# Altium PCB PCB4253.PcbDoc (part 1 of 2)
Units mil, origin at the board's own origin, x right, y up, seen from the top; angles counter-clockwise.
Board outline 1181.1 x 2007.87 mil, 6 copper layers (Top Layer, Signal Layer 2, GND Layer 3, PWR Layer 4, Signal Layer 5, Bottom Layer), stack 65.197 mil thick; 84 components, 108 nets, 396 pads, 435 vias.
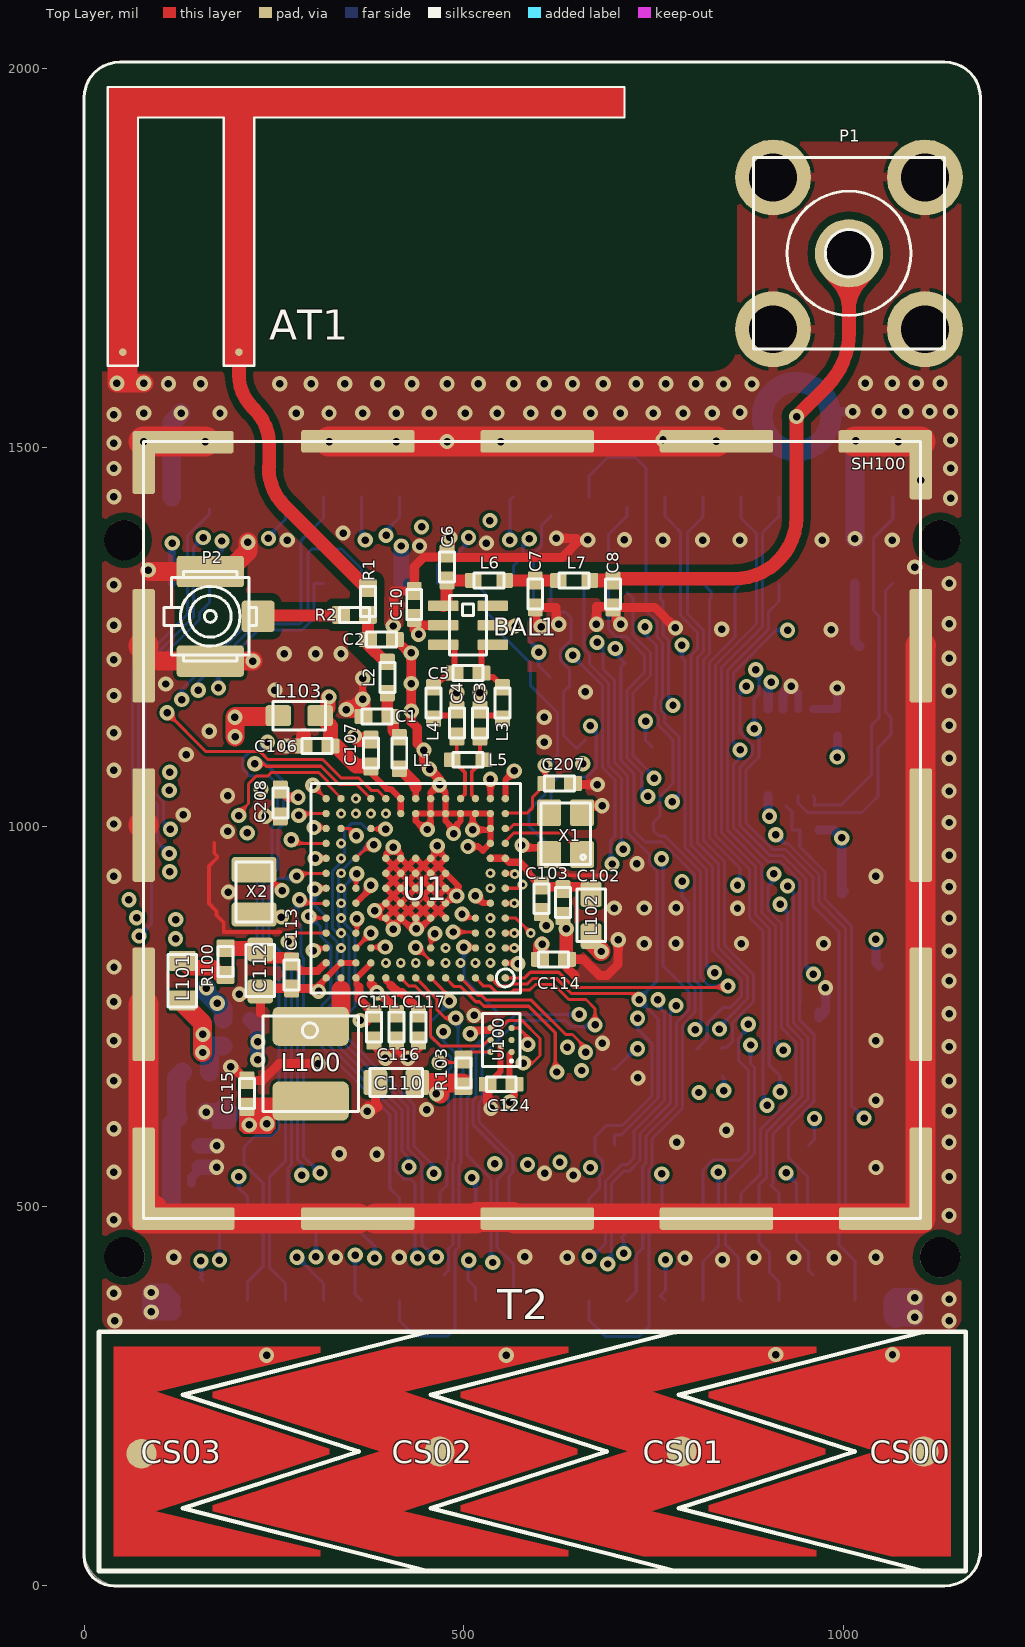
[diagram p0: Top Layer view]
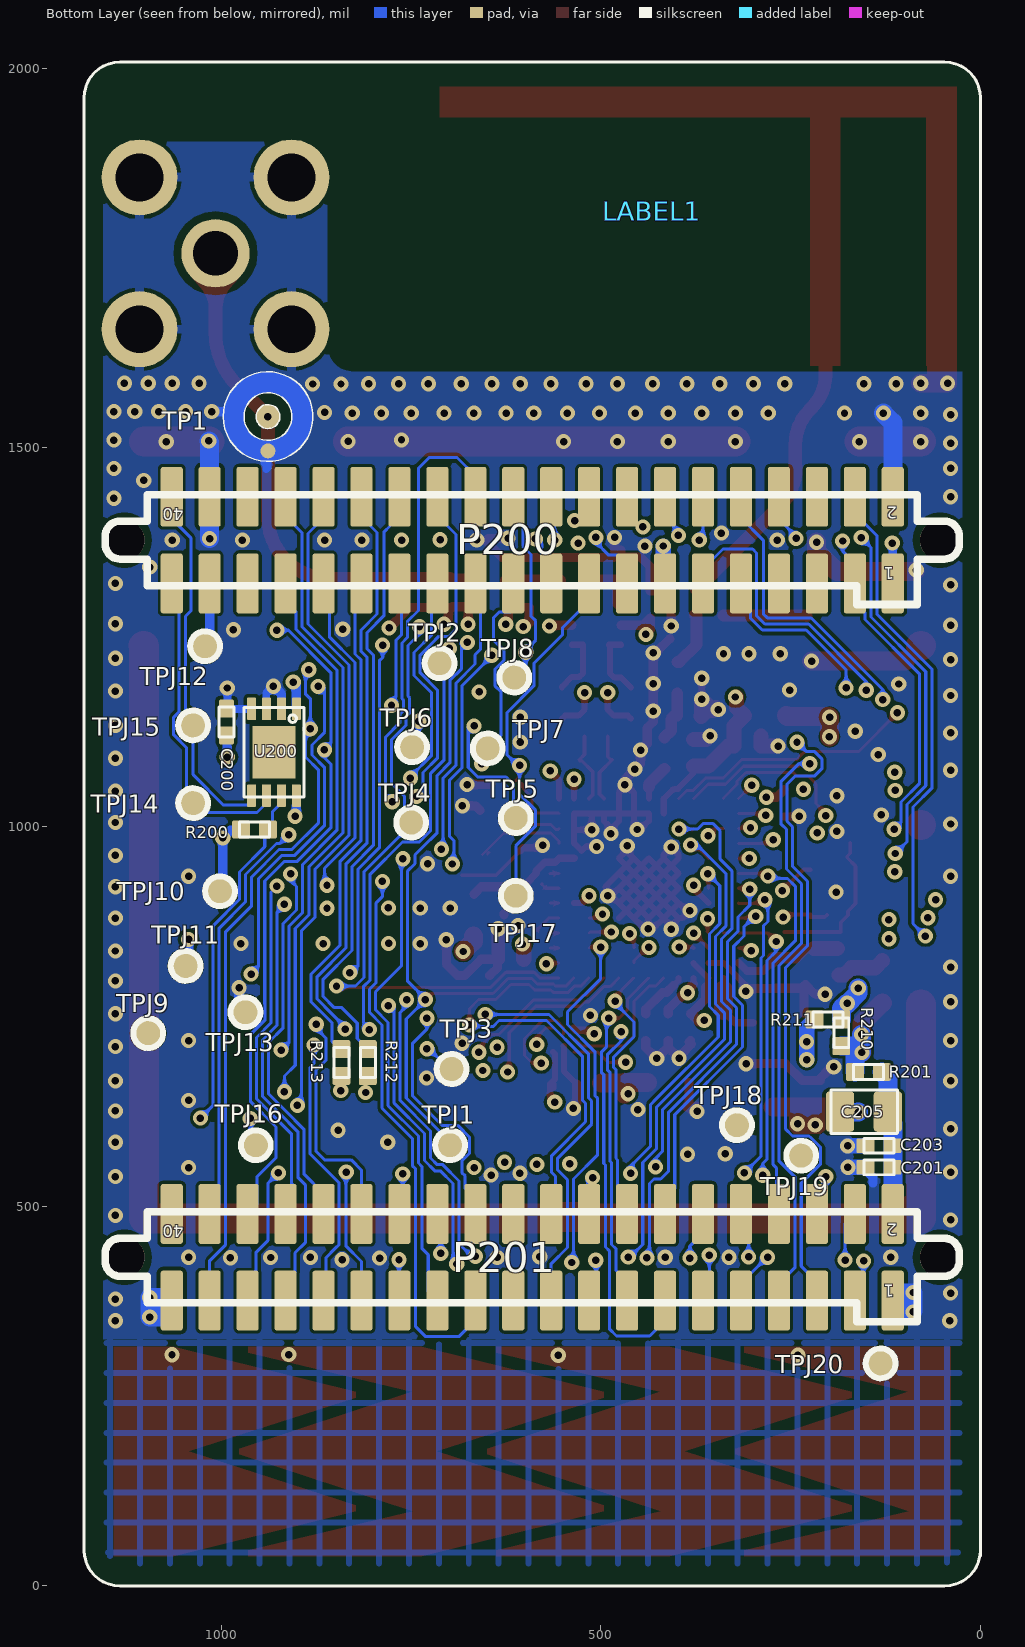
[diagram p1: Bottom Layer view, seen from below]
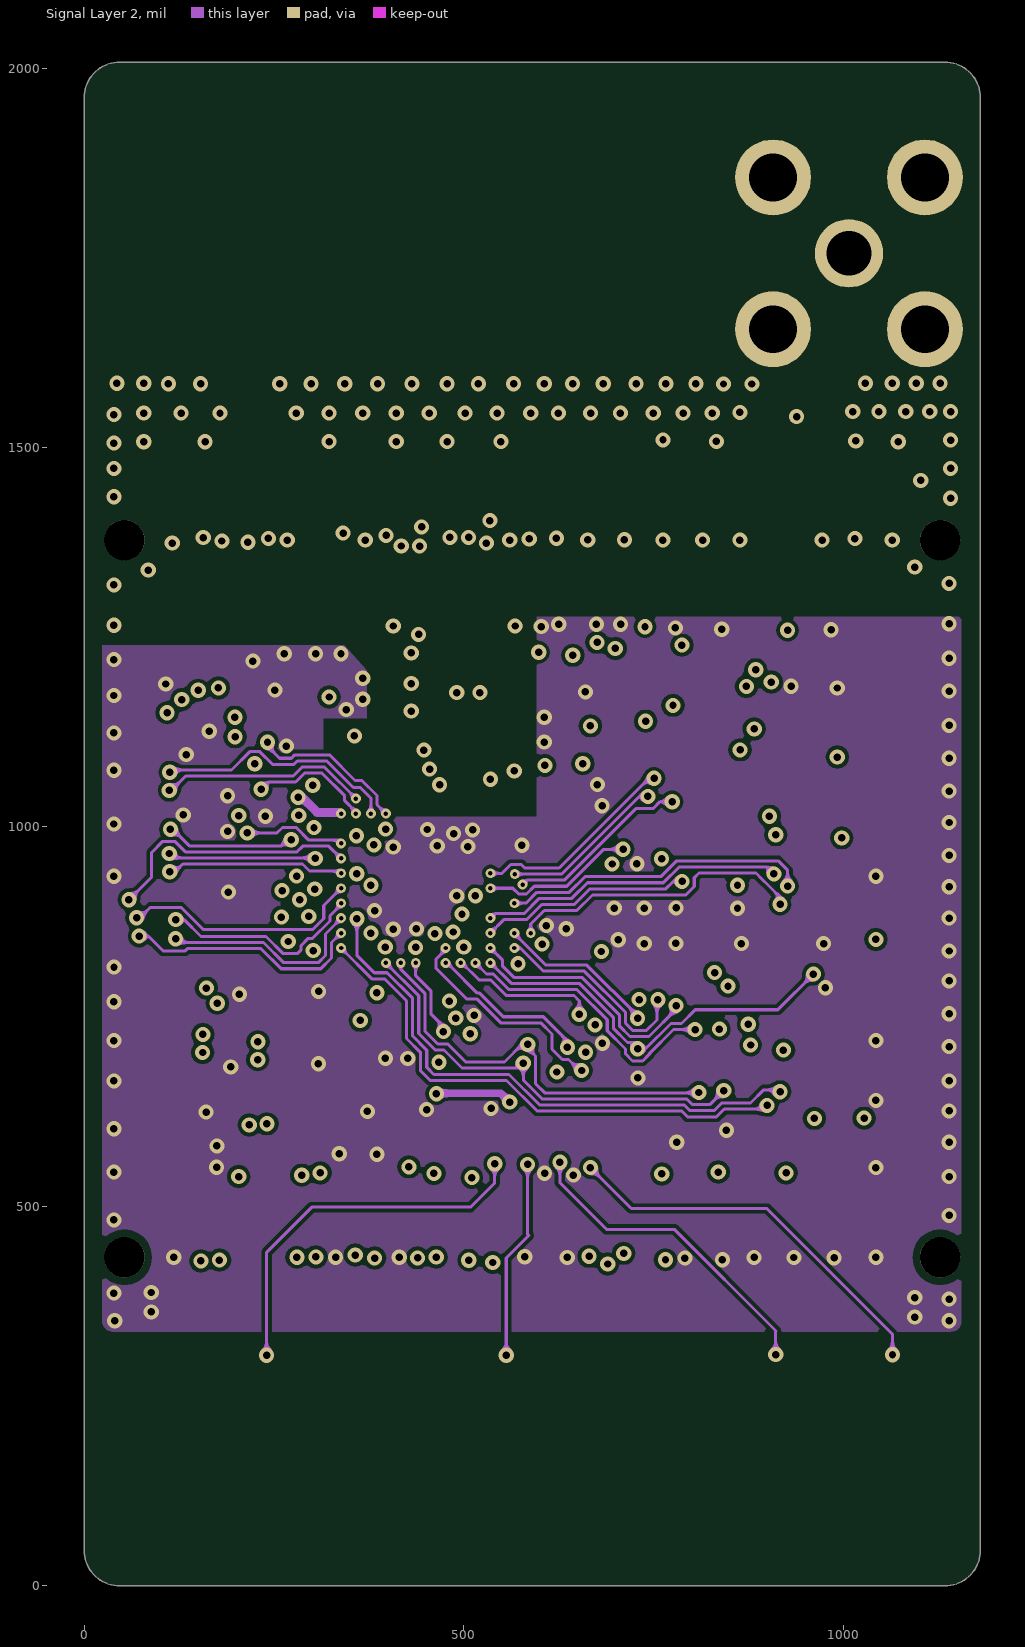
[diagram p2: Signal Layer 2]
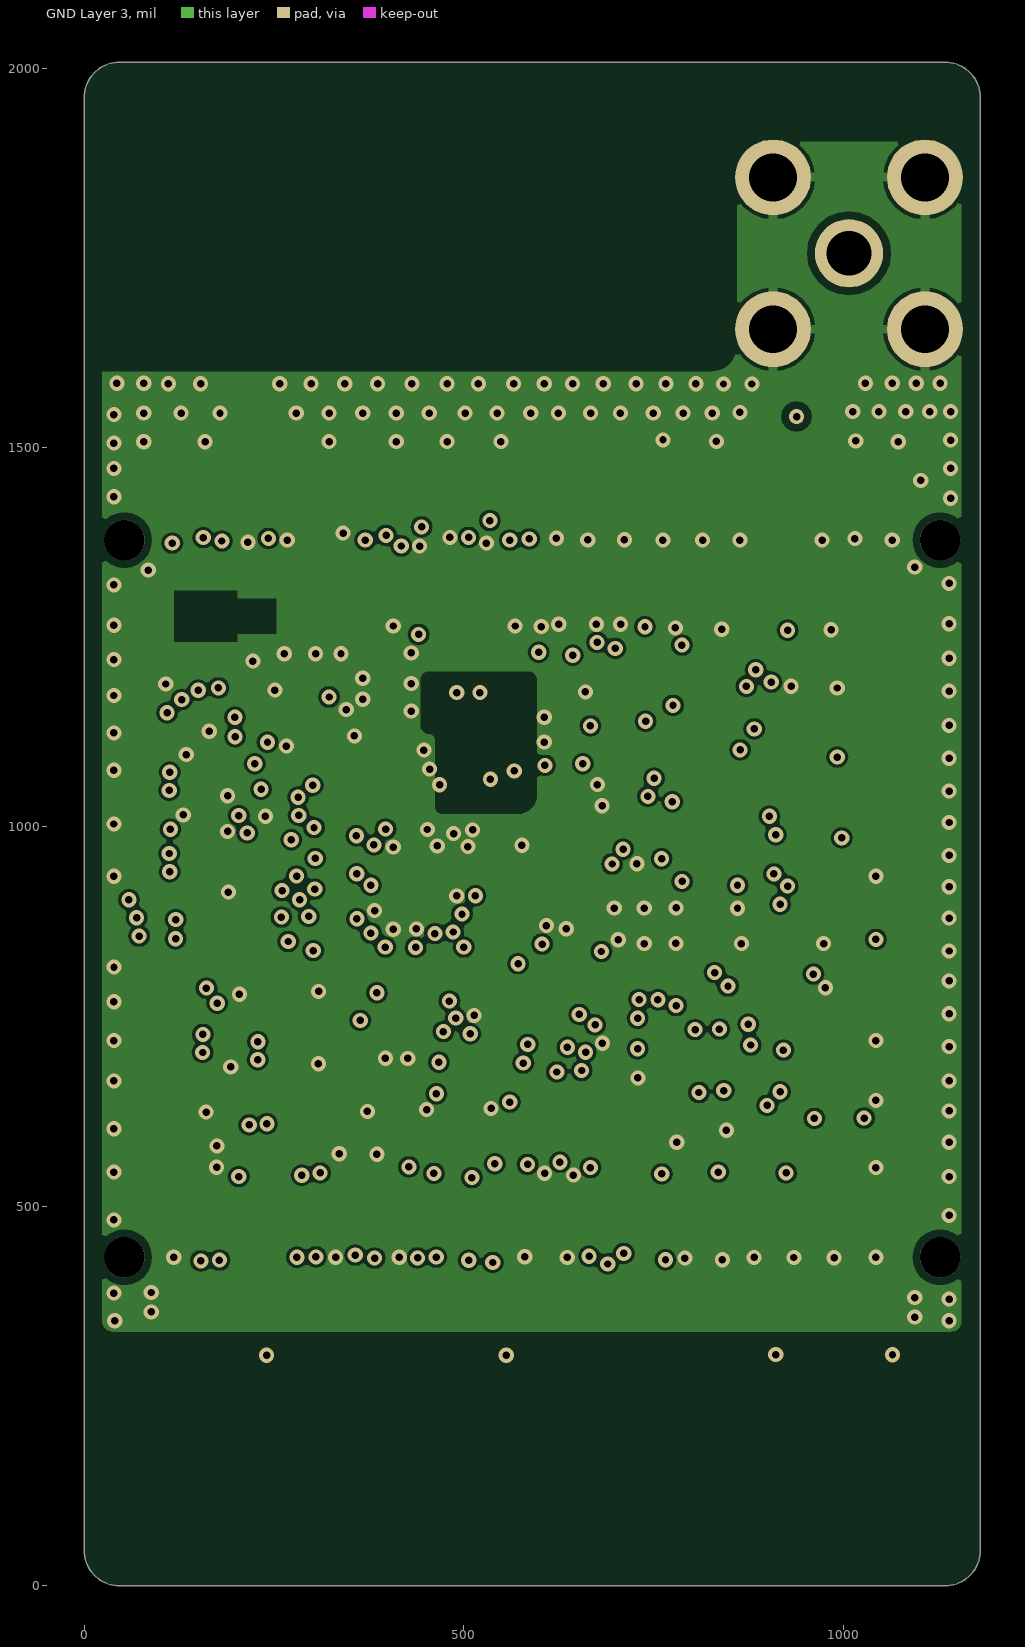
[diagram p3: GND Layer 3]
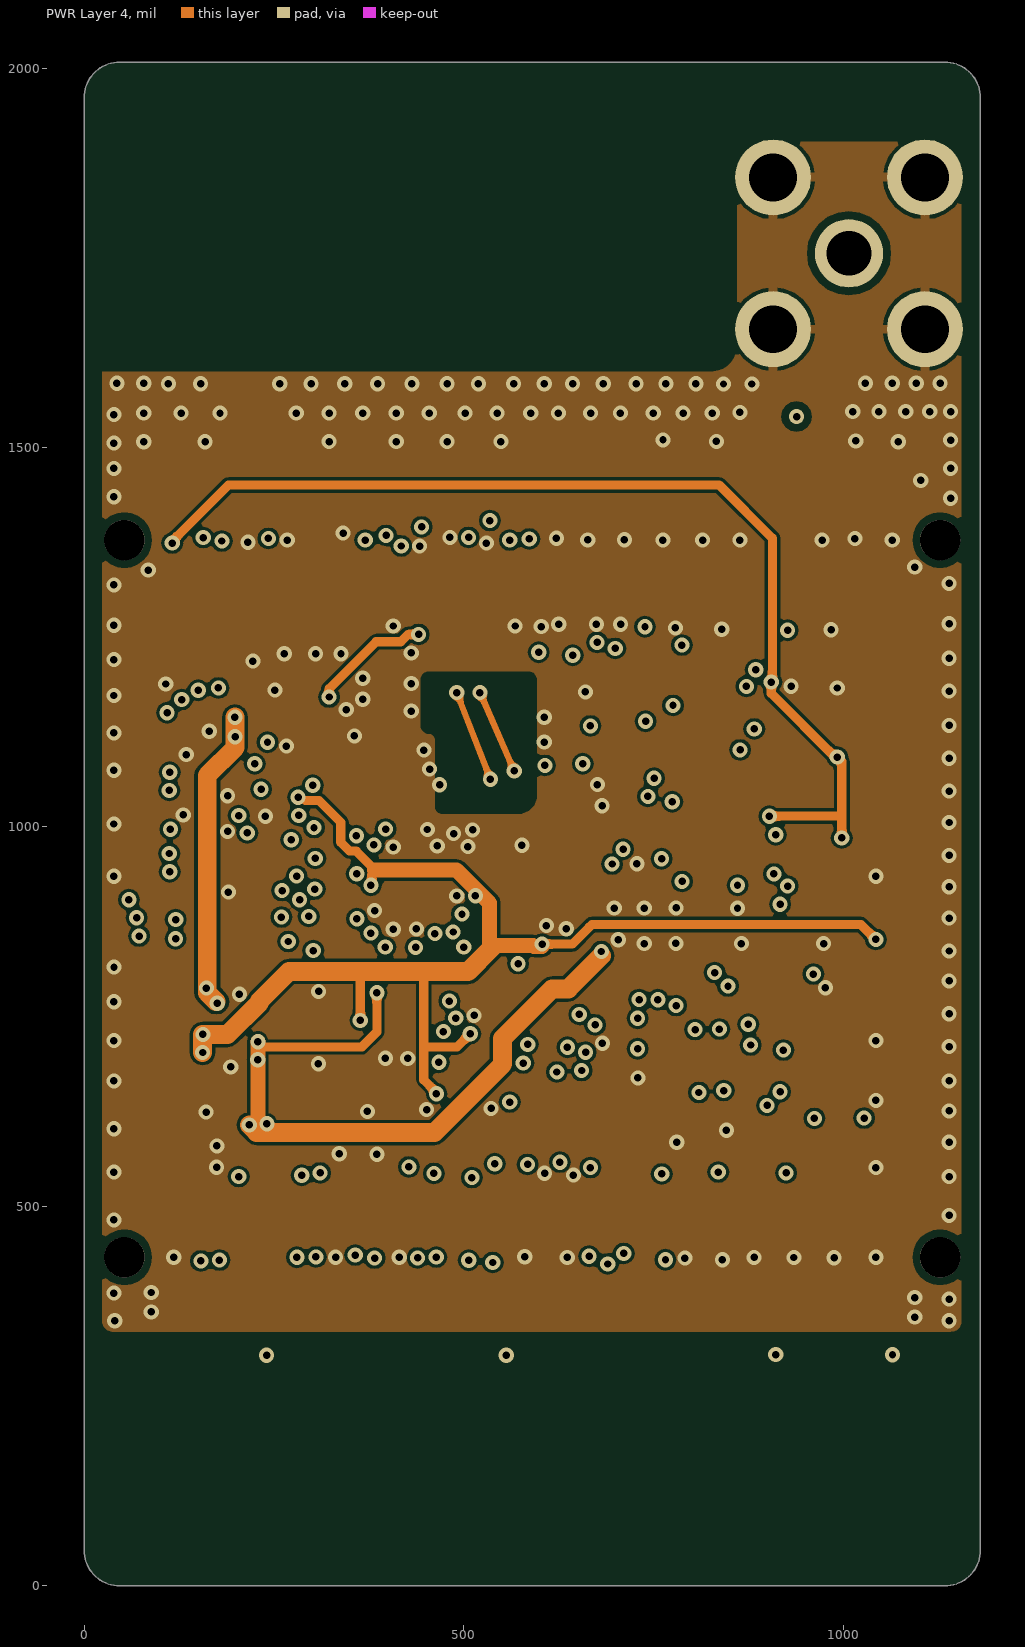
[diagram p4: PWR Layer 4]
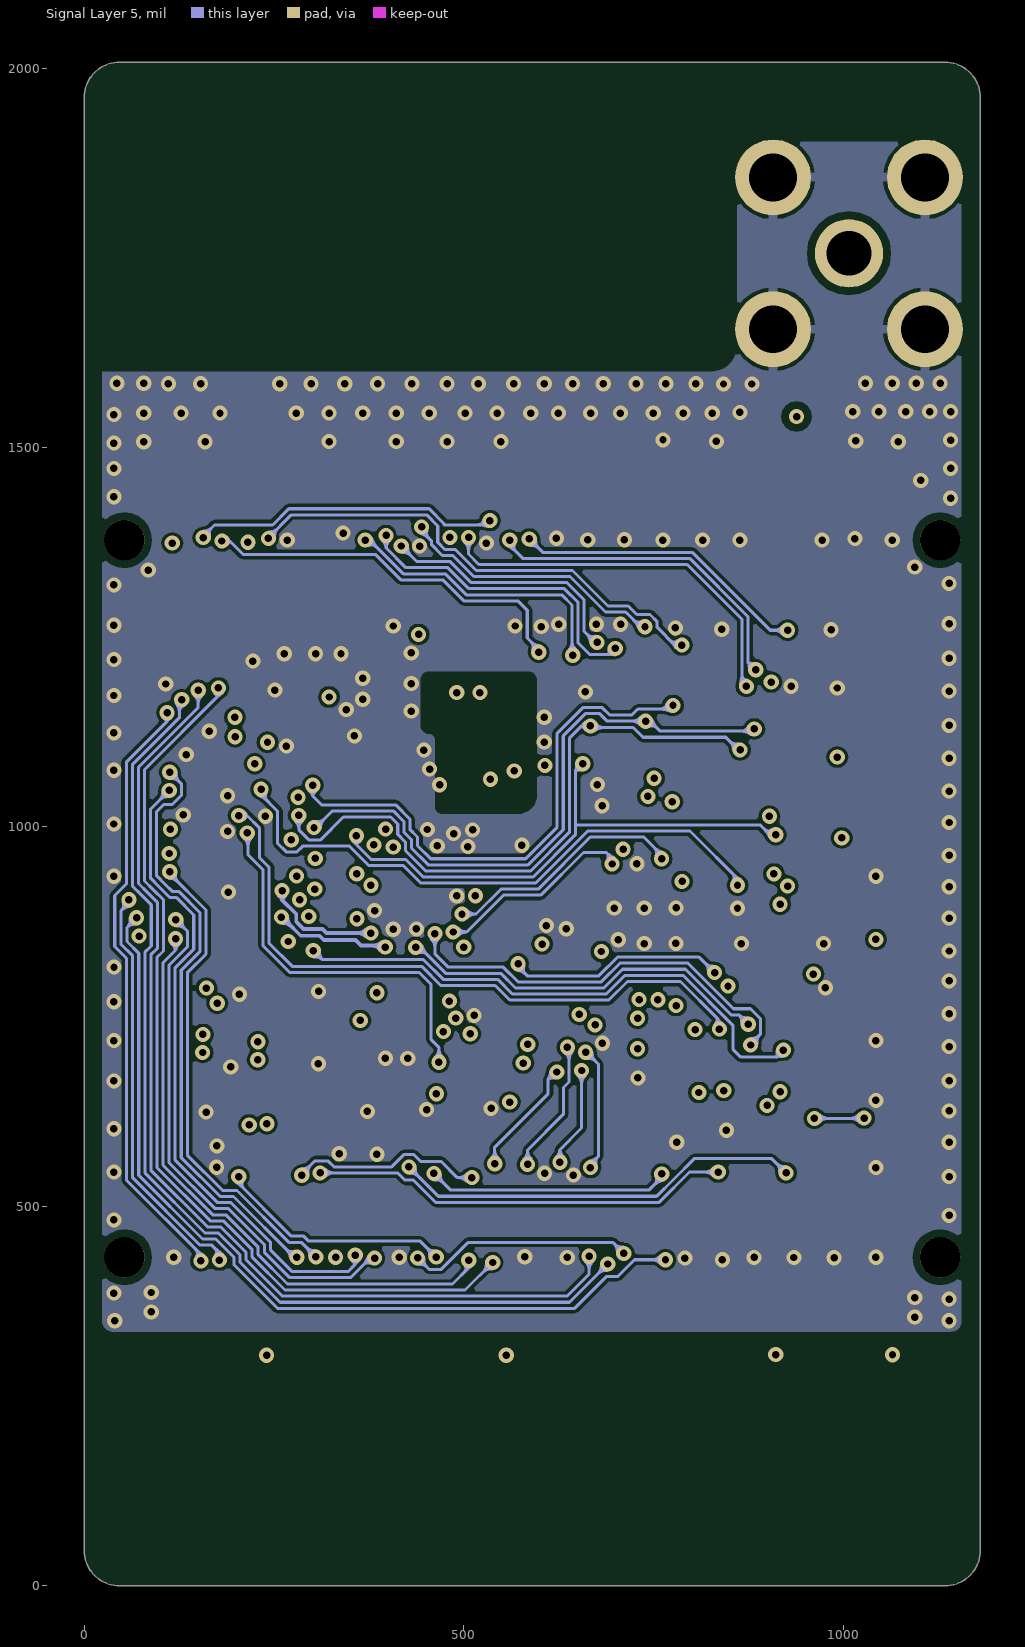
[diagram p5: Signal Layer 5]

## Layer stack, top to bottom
Top Solder: solder mask 0.3937, Solder Resist, Dk 3.5
Top Layer: signal copper 1.378
Dielectric 1: prepreg 3.5433, FR-4, Dk 4.2
Signal Layer 2: signal copper 1.378
Dielectric 2: core 7.0866, Dk 4.2
GND Layer 3: signal copper 1.378
Dielectric 3: prepreg 35.6693, FR-4, Dk 4.2
PWR Layer 4: signal copper 1.378
Dielectric 5: core 7.0866, Dk 4.2
Signal Layer 5: signal copper 1.378
Dielectric 6: prepreg 3.5433, Dk 4.2
Bottom Layer: signal copper 1.378
Bottom Solder: solder mask 0.3937, Solder Resist, Dk 3.5

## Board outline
0,47.24 ccw(c47.24,47.24) 47.24,0 1133.86,0 ccw(c1133.86,47.24) 1181.1,47.24 1181.1,1960.63 ccw(c1133.86,1960.63) 1133.86,2007.87 47.24,2007.87 ccw(c47.24,1960.63) 0,1960.63

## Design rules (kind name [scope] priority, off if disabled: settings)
Clearance Clearance_to_Holes [InPadClass('NPTH')] p1: gap=10
Clearance Clearance_NetP2_1 [InNet('NetP2_1')] p2: gap=9.84
Clearance Clearance_NetC8 [InNet('NetC8_1')] p3: gap=9.84
Clearance Clearance_Net_AT1_1 [InNet('NetAT1_1')] p4: gap=9.84
Clearance Clerance_Polygon_GND3 [InNamedPolygon('GND_3')] p5: gap=5
Clearance Clerance_Polygon_GND2 [InNamedPolygon('GND_2')] p6: gap=5
Clearance Clerance_Polygon_GND1 [InNamedPolygon('GND_L2')] p7: gap=5
Clearance Clerance_Polygon_GND4 [InNamedPolygon('GND_4')] p8: gap=5
Clearance Clearance_General [All] p9: gap=4
HoleToHoleClearance HoleToHoleClearance_ANT1toPAD [Incomponent ('ANT1') vs ISpad] p1: gap=0 allowstackedmicrovias=TRUE
HoleToHoleClearance HoleToHoleClearance_U1toVIA_1 [InComponent ('U1') vs IsVia] p2: gap=0 allowstackedmicrovias=TRUE
HoleToHoleClearance [All] p3: gap=10 allowstackedmicrovias=TRUE
MinimumSolderMaskSliver [All] p1: minsoldermaskwidth=4
PolygonConnect PolygonConnect_SH100 [InComponent('SH100')] p1: connectstyle=Direct reliefconductorwidth=10 reliefentries=4 polygonreliefangle="90 Angle" airgapwidth=5
PolygonConnect PolygonConnect_P1 [InComponent('P1')] p2: connectstyle=Relief reliefconductorwidth=12 reliefentries=4 polygonreliefangle="90 Angle" airgapwidth=5
PolygonConnect Polygon_VIA_Connect [IsVia] p3: connectstyle=Direct reliefconductorwidth=10 reliefentries=4 polygonreliefangle="90 Angle" airgapwidth=10
PolygonConnect PolygonConnect_General [All] p4: connectstyle=NoConnect reliefconductorwidth=10 reliefentries=4 polygonreliefangle="90 Angle" airgapwidth=5
RoutingVias [All] p1: holewidth=9.84 width=20 viastyle="Through Hole" minholewidth=9.84 minwidth=20 maxholewidth=39.37 maxwidth=59.06
SilkToSilkClearance [All] p1: silktosilkclearance=4
SilkToSolderMaskClearance [IsPad] p1: minsilkscreentomaskgap=4 clearancetoexposedcopper=TRUE
SolderMaskExpansion [All] p1: expansion=2
Width [All] p1: maxlimit=200 minlimit=4 preferedwidth=5
26 further rules are at their usual default settings.

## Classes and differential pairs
net class WSTK_P[45..0]: WSTK_P18 WSTK_P19 WSTK_P32 WSTK_P38 WSTK_P39 WSTK_P40
net class WSTK_F[21..0]: WSTK_F4 WSTK_F15 WSTK_F16
net class RADIO_PF[15..0]: RADIO_PF0 RADIO_PF1 RADIO_PF2 RADIO_PF3 RADIO_PF4 RADIO_PF5 RADIO_PF6 RADIO_PF7 RADIO_PF8 RADIO_PF9 RADIO_PF10 RADIO_PF11 RADIO_PF12 RADIO_PF13 RADIO_PF14 RADIO_PF15
net class RADIO_PD[15..8]: RADIO_PD8 RADIO_PD9 RADIO_PD10 RADIO_PD11 RADIO_PD12 RADIO_PD13 RADIO_PD14 RADIO_PD15
net class RADIO_PC[11..0]: RADIO_PC0 RADIO_PC1 RADIO_PC2 RADIO_PC3 RADIO_PC4 RADIO_PC5 RADIO_PC6 RADIO_PC7 RADIO_PC8 RADIO_PC9 RADIO_PC10 RADIO_PC11
net class RADIO_PB[15..6]: RADIO_PB6 RADIO_PB7 RADIO_PB8 RADIO_PB9 RADIO_PB10 RADIO_PB11 RADIO_PB12 RADIO_PB13 RADIO_PB14 RADIO_PB15
net class RADIO_PA[9..0]: RADIO_PA0 RADIO_PA1 RADIO_PA2 RADIO_PA3 RADIO_PA4 RADIO_PA5 RADIO_PA6 RADIO_PA7 RADIO_PA8 RADIO_PA9
component class "04_ WSTK Connectors & B": C200 C201 C203 C205 R200 R201 TPJ1 TPJ2 TPJ3 TPJ4 TPJ5 TPJ6 TPJ7 TPJ8 TPJ9 TPJ10 TPJ11 TPJ12 TPJ13 TPJ14 TPJ15 TPJ16 TPJ17 TPJ18 TPJ19 TPJ20 U200
component class "03_ EFR32 Signal Assign": 180 C124 C207 R103 R203 R204 R213 RP200 T2 U1
component class "02_ RF, Antenna & Power": AT1 BAL1 C1 C2 C3 C4 C5 C6 C7 C8 C10 C102 C103 C106 C107 C110 C111 C112 C113 C114 C115 C116 C117 C208 L1 L2 L3 L4 L5 L6 L7 L100 L101 L102 L103 P1 P2 R1 R2 R100 R210 R211 SH100 TP1 X1 X2
component class "01_ Title Page": PCB1
net class RADIO_PI[3..0]: RADIO_PI0 RADIO_PI1 RADIO_PI2 RADIO_PI3
net class RADIO_PJ[15..14]: RADIO_PJ14 RADIO_PJ15
net class RADIO_PK[2..0]: RADIO_PK0 RADIO_PK1 RADIO_PK2
pad class NPTH: P200-M1 P200-M2 P201-M1 P201-M2

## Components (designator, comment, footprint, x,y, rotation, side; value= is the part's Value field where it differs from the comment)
AT1 "INVERTED_F" ANT_INV_F_2.4_GHZ_17.3MM_MIR 31.1,1607.87 r0 top locked net-tie
BAL1 "0900BL15C050" BALUN_JOH_0900BL15 505.91,1265.75 r0 top
C1 "cfg" C0402_L 385.83,1145.67 r0 top
C2 "cfg" C0402_L 391.73,1247.05 r180 top
C3 "cfg" C0402_L 521.65,1136.81 r270 top
C4 "cfg" C0402_L 491.14,1136.81 r270 top
C5 "cfg" C0402_L 505.91,1202.76 r180 top
C6 "cfg" C0402_L 478.35,1342.52 r90 top
C7 "cfg" C0402_L 594.49,1307.09 r270 top
C8 "cfg" C0402_L 696.85,1307.09 r270 top
C10 "cfg" C0402_L 435.04,1293.31 r90 top
C102 "100P" C0402_L 631.1,900.34 r270 top
C103 "10P" C0402_L 602.59,905.44 r270 top
C106 "220N" C0402_L 306.81,1106.57 r180 top
C107 "10P" C0402_L 377.95,1097.44 r90 top
C110 "10U" C0603_L 411.42,663.39 r180 top
C111 "1U" C0402_L 381.89,736.22 r270 top
C112 "10U" C0603_L 232.28,811.02 r270 top
C113 "10N" C0402_L 273.62,805.12 r270 top
C114 "1U" C0402_L 618.54,825.66 r0 top
C115 "4U7" C0402_L 214.57,648.62 r90 top
C116 "100N" C0402_L 411.42,736.22 r270 top
C117 "1U" C0402_L 440.95,736.22 r270 top
C124 "100N" C0402_L 549.66,661.05 r180 top
C200 "100N" C0402_L 993.39,1138.37 r90 bottom
C201 "100N" C0402_L 133.86,551.64 r0 bottom
C203 "100N" C0402_L 133.86,579.99 r0 bottom
C205 "10U" C0805_L 153.54,625 r0 bottom
C207 "100N" C0402_L 626.68,1057.35 r0 top
C208 "100N" C0402_L 258.61,1031.55 r270 top
L1 "cfg" COIL_0402_L 415.35,1097.44 r90 top
L2 "cfg" COIL_0402_L 399.61,1196.85 r90 top
L3 "cfg" COIL_0402_L 551.18,1163.39 r270 top
L4 "cfg" COIL_0402_L 460.63,1163.39 r270 top
L5 "cfg" COIL_0402_L 505.91,1088.58 r0 top
L6 "cfg" COIL_0402_L 533.46,1324.8 r180 top
L7 "cfg" COIL_0402_L 645.67,1324.8 r180 top
L100 "4U7" COIL_MUR_LQH3NP_1212 298.59,688.08 r270 top
L101 "CBF102WB" COIL_WURTH_CBF_0603_L 129.37,797.53 r90 top
L102 "BLM18AG601SN1" COIL_MUR_BLM18_0603 668.2,883.69 r90 top
L103 "BLM18AG601SN1" COIL_MUR_BLM18_0603 283.46,1146.65 r0 top
LABEL1 "Comment" LABEL_4CORNERS_19.0X6.0 433.07,1811.02 r180 bottom
P1 "SMA" TE_SMA_1814832_TH_VER 1007.87,1755.9 r0 top locked
P2 "U.FL" COAX_HIROSE_U.FL_CL331-0471 166.34,1277.56 r270 top
P200 "SOCKET_2X20_1.27MM_SMD" SAM_SFC-120-T2-D-A-2X20_SNUM 590.55,1377.95 r0 bottom
P201 "SOCKET_2X20_1.27MM_SMD" SAM_SFC-120-T2-D-A-2X20_SNUM 590.55,433.07 r0 bottom
R1 "0R" R0402_L 374.02,1297.24 r90 top
R2 "0R" R0402_L 356.3,1279.53 r180 top
R100 "1R" R0402_L 186.5,822.54 r90 top
R103 "330K" R0402_L 499.79,676.08 r90 top
R200 "10K" R0402_L 956.5,996.6 r0 bottom
R201 "0R" R0402_L 147.64,677.17 r0 bottom
R210 "0R" R0402_L 183.39,728.96 r270 bottom
R211 "0R" R0402_L 201.11,746.28 r0 bottom
R212 "100R" R0402_L 807.24,689.59 r90 bottom
R213 "100R" R0402_L 842.11,689.77 r90 bottom
SH100 "RF_SHIELD_FRAME_BMI-S-203-F" RF_SHIELD_FRAME_BMI-S-203-F_PCB4100 590.55,996.06 r0 top locked
T2 "TOUCH SLIDER" TOUCH_SLIDER2_28.0X7.0-4 19.69,19.69 r0 top
TP1 "RF_TEST_POINT" TP_INGUN_50_OHM_CLOSED 938.78,1540.75 r180 bottom
TPJ1 "TPJ_SMD" TP_1.0_SMD 698.82,580.71 r90 bottom
TPJ2 "TPJ_SMD" TP_1.0_SMD 712.6,1215.75 r90 bottom
TPJ3 "TPJ_SMD" TP_1.0_SMD 696.85,681.1 r90 bottom
TPJ4 "TPJ_SMD" TP_1.0_SMD 750,1005.91 r90 bottom
TPJ5 "TPJ_SMD" TP_1.0_SMD 612.2,1011.81 r90 bottom
TPJ6 "TPJ_SMD" TP_1.0_SMD 748.82,1105.12 r90 bottom
TPJ7 "TPJ_SMD" TP_1.0_SMD 649.21,1103.54 r90 bottom
TPJ8 "TPJ_SMD" TP_1.0_SMD 614.17,1196.85 r90 bottom
TPJ9 "TPJ_SMD" TP_1.0_SMD 1096.46,728.35 r90 bottom
TPJ10 "TPJ_SMD" TP_1.0_SMD 1001.97,915.35 r90 bottom
TPJ11 "TPJ_SMD" TP_1.0_SMD 1047.24,816.93 r90 bottom
TPJ12 "TPJ_SMD" TP_1.0_SMD 1021.65,1238.19 r90 bottom
TPJ13 "TPJ_SMD" TP_1.0_SMD 968.5,755.91 r90 bottom
TPJ14 "TPJ_SMD" TP_1.0_SMD 1037.4,1031.5 r90 bottom
TPJ15 "TPJ_SMD" TP_1.0_SMD 1037.4,1133.86 r90 bottom
TPJ16 "TPJ_SMD" TP_1.0_SMD 954.72,580.71 r90 bottom
TPJ17 "TPJ_SMD" TP_1.0_SMD 612.2,909.45 r90 bottom
TPJ18 "TPJ_SMD" TP_1.0_SMD 320.87,607.09 r90 bottom
TPJ19 "TPJ_SMD" TP_1.0_SMD 236.22,566.93 r90 bottom
TPJ20 "TPJ_SMD" TP_1.0_SMD 131.5,293.31 r90 bottom
U1 "EFR32MG2_BGA125_0A" BGA125_M050_7.0X7.0 437.01,919.29 r180 top
U100 "MX25R8035F" BGA8_M040_1.24x1.75_WLCSP 549.51,719.31 r180 top
U200 "24AA024" TDFN8_M050_2.0X3.0_EP 930.8,1098.47 r270 bottom
X1 "38.400 MHz" X_SSS_DSX211SH_2.05X1.65-4 634.53,991.23 r90 top
X2 "32.768kHz" X_MCS_CM8V-T1A 224.08,914.32 r90 top

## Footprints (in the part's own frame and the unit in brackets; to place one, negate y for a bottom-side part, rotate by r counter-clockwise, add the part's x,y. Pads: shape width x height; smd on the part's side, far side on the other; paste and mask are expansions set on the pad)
ANT_INV_F_2.4_GHZ_17.3MM_MIR [mil] "Antenna inverted F, 2.4 GHz, 17.3 mm (MIR)"
  round 10 smd paste-5 mask-5: 1(173,17.72) 2(20.01,17.72)
  Top Layer region: 0.36,367.2 681,367.2 681,327.07 193.36,327.07 193.36,0 153.36,0 153.36,327.07 40.36,327.07 40.36,0 20.36,0 0.36,0
  silkscreen extent 0,0 681,367
BALUN_JOH_0900BL15 [mil] "BALUN JOHANSON 0900BL15 0805"
  rrect20% 40x14 smd: 1(-32.5,25.59) 2(-32.5,0) 3(-32.5,-25.59) 4(32.5,-25.59) 5(32.5,0) 6(32.5,25.59)
  silkscreen extent -25,-39 25,39, body extent -27,-41 27,41, height 32
BGA8_M040_1.24x1.75_WLCSP [mm] "BGA, 8 pin. U100"
  round 0.21 smd mask+0.051: A1(-0.35,0.4) A3(0.35,0.4) B2(0,0.2) C1(-0.35,0) C3(0.35,0) D2(0,-0.2) E1(-0.35,-0.4) E3(0.35,-0.4)
  silkscreen extent -0.63,-0.89 0.63,0.88, body extent -0.63,-0.89 0.63,0.88, height 0.52
BGA125_M050_7.0X7.0 [mm] "(BGA125N7X7P0.5)"
  round 0.25 smd: A1(-3,3) A2(-2.5,3) A3(-2,3) A4(-1.5,3) A5(-1,3) A6(-0.5,3) A7(0,3) A8(0.5,3) A9(1,3) A10(1.5,3) A11(2,3) A12(2.5,3) A13(3,3) B1(-3,2.5) B2(-2.5,2.5) B3(-2,2.5) B4(-1.5,2.5) B5(-1,2.5) B6(-0.5,2.5) B7(0,2.5) B8(0.5,2.5) B9(1,2.5) B10(1.5,2.5) B11(2,2.5) B12(2.5,2.5) B13(3,2.5) C1(-3,2) C2(-2.5,2) C3(-2,2) C5(-1,2) C6(-0.5,2) C10(1.5,2) C11(2,2) C12(2.5,2) C13(3,2) D1(-3,1.5) D2(-2.5,1.5) D3(-2,1.5) D11(2,1.5) D12(2.5,1.5) D13(3,1.5) E1(-3,1) E2(-2.5,1) E3(-2,1) E5(-1,1) E6(-0.5,1) E7(0,1) E8(0.5,1) E9(1,1) E12(2.5,1) E13(3,1) F1(-3,0.5) F2(-2.5,0.5) F5(-1,0.5) F6(-0.5,0.5) F7(0,0.5) F8(0.5,0.5) F9(1,0.5) F11(2,0.5) F12(2.5,0.5) F13(3,0.5) G1(-3,0) G2(-2.5,0) G5(-1,0) G6(-0.5,0) G7(0,0) G8(0.5,0) G9(1,0) G11(2,0) G12(2.5,0) G13(3,0) H1(-3,-0.5) H2(-2.5,-0.5) H5(-1,-0.5) H6(-0.5,-0.5) H7(0,-0.5) H8(0.5,-0.5) H9(1,-0.5) H12(2.5,-0.5) H13(3,-0.5) J1(-3,-1) J2(-2.5,-1) J5(-1,-1) J6(-0.5,-1) J7(0,-1) J8(0.5,-1) J9(1,-1) J11(2,-1) J12(2.5,-1) J13(3,-1) K1(-3,-1.5) K2(-2.5,-1.5) K12(2.5,-1.5) K13(3,-1.5) L1(-3,-2) L2(-2.5,-2) L10(1.5,-2) L12(2.5,-2) L13(3,-2) M1(-3,-2.5) M2(-2.5,-2.5) M3(-2,-2.5) M4(-1.5,-2.5) M5(-1,-2.5) M6(-0.5,-2.5) M7(0,-2.5) M8(0.5,-2.5) M9(1,-2.5) M10(1.5,-2.5) M11(2,-2.5) M12(2.5,-2.5) M13(3,-2.5) N1(-3,-3) N2(-2.5,-3) N3(-2,-3) N4(-1.5,-3) N5(-1,-3) N6(-0.5,-3) N7(0,-3) N8(0.5,-3) N9(1,-3) N10(1.5,-3) N11(2,-3) N12(2.5,-3) N13(3,-3)
  silkscreen extent -3.5,-3.5 3.5,3.5, body extent -3.5,-3.5 3.5,3.5, height 1.01
C0402_L [mm] "Chip Capacitor, 2-Leads, Body 1.0x0.5mm, IPC High Density"
  rrect20% 0.6x0.5 smd mask+0.051: 1(-0.45,0) 2(0.45,0)
  silkscreen extent -0.5,-0.25 0.5,0.25, body extent -0.5,-0.25 0.5,0.25, height 0.6
C0603_L [mm] "Capacitor, 0603, High Density (C)"
  rrect25% 0.8x0.85 smd: 1(-0.7,0) 2(0.7,0)
  silkscreen extent -0.88,-0.48 0.87,0.48, body extent -0.88,-0.48 0.87,0.48, height 0.95
C0805_L [mm] "Capacitor, 0805"
  rrect25% 0.95x1.35 smd: 1(-0.8,0) 2(0.8,0)
  silkscreen extent -1.12,-0.72 1.1,0.72, body extent -1.1,-0.72 1.1,0.72, height 1.45
COAX_HIROSE_U.FL_CL331-0471 [mm] "COAX_HIROSE_U.FL_CL331-0471"
  rrect20% 1.05x1.1 smd mask+0.051: 1(0,1.6)
  rrect20% 1.05x2.25 smd mask+0.051: 2(-1.5,0) 3(1.5,0)
  Top Layer pour cut-out: -0.85,0.9 0.85,0.9 0.85,0.9 0.85,-1.2 -0.85,-1.2 -0.85,-1.2
  silkscreen extent -1.5,-1.55 1.5,1.55, body extent -1.3,-1.55 1.3,1.3, height 0.9
COIL_0402_L [mm] "COIL_0402_L"
  rrect20% 0.55x0.5 smd mask+0.051: 1(-0.525,0) 2(0.525,0)
  silkscreen extent -0.5,-0.25 0.5,0.25, body extent -0.5,-0.25 0.5,0.25, height 0.6
COIL_MUR_BLM18_0603 [mm] "COIL_MUR_BLM18P_0603"
  rrect25% 0.85x0.7 smd mask+0.051: 1(-0.7,0) 2(0.7,0)
  silkscreen extent -0.88,-0.48 0.87,0.48, body extent -0.88,-0.48 0.87,0.48, height 0.95
COIL_MUR_LQH3NP_1212 [mm] "COIL_MUR_LQH3NP_1212"
  rrect30% 1.3x2.55 smd mask+0.051: 1(-1.25,0) 2(1.25,0)
  silkscreen extent -1.6,-1.6 1.6,1.6, body extent -1.6,-1.6 1.6,1.6, height 1.5
COIL_WURTH_CBF_0603_L [mm] "COIL_WURTH_CBF_0603_L (= L0603_0.8_L)"
  rrect10% 0.67x0.88 smd: 1(-0.665,0) 2(0.665,0)
  silkscreen extent -0.87,-0.48 0.87,0.48, body extent -0.87,-0.48 0.87,0.48, height 0.95
LABEL_4CORNERS_19.0X6.0 [mil]
R0402_L [mm] "Chip Resistor, 2-Leads, Body 1.0x0.5mm, IPC High Density"
  rrect20% 0.6x0.6 smd mask+0.051: 1(-0.45,0) 2(0.45,0)
  silkscreen extent -0.5,-0.25 0.5,0.25, body extent -0.5,-0.25 0.5,0.25, height 0.6
RF_SHIELD_FRAME_BMI-S-203-F_PCB4100 [mm] "RF_SHIELD_FRAME_BMI-S-203-F"
  rrect20% 0.75x3.8 smd paste+0 mask+0.05: 1(-13.005,-5.835) 1(-13.005,0.165) 1(-13.005,6.165) 1(13.005,-5.835) 1(13.005,0.165) 1(13.005,6.165)
  rrect20% 0.75x3.4 smd paste+0 mask+0.05: 1(-13.005,-11.659) 1(13.005,-11.659)
  rrect20% 0.75x2.1 smd paste+0 mask+0.05: 1(-13.005,12.294)
  oval 0.75x0.254 smd paste+0 mask+0.05: 1(-13.004,12.994) 1(12.994,12.994) 1(12.994,12.994) 1(12.994,12.994)
  rrect20% 3.375x0.75 smd paste+0 mask+0.05: 1(-11.684,12.979)
  rrect20% 3.4x0.75 smd paste+0 mask+0.05: 1(-11.659,-13.005)
  rrect20% 3.8x0.75 smd paste+0 mask+0.05: 1(-5.835,-13.005) 1(-5.835,13.005) 1(0.165,-13.005) 1(0.165,13.005) 1(6.165,-13.005) 1(6.165,13.005)
  rrect20% 3.1x0.75 smd paste+0 mask+0.05: 1(11.811,-13.005)
  rrect20% 3.125x0.75 smd paste+0 mask+0.05: 1(11.811,13.005)
  rrect20% 0.75x2.3 smd paste+0 mask+0.05: 1(13.005,12.217)
  silkscreen extent -13.01,-13.01 13,13, body extent -13,-13 12.99,12.99, height 5.08
SAM_SFC-120-T2-D-A-2X20_SNUM [mm]
  rrect20% 0.74x2 smd mask+0.05: 1(-12.065,1.45) 2(-12.065,-1.45) 3(-10.795,1.45) 4(-10.795,-1.45) 5(-9.525,1.45) 6(-9.525,-1.45) 7(-8.255,1.45) 8(-8.255,-1.45) 9(-6.985,1.45) 10(-6.985,-1.45) 11(-5.715,1.45) 12(-5.715,-1.45) 13(-4.445,1.45) 14(-4.445,-1.45) 15(-3.175,1.45) 16(-3.175,-1.45) 17(-1.905,1.45) 18(-1.905,-1.45) 19(-0.635,1.45) 20(-0.635,-1.45) 21(0.635,1.45) 22(0.635,-1.45) 23(1.905,1.45) 24(1.905,-1.45) 25(3.175,1.45) 26(3.175,-1.45) 27(4.445,1.45) 28(4.445,-1.45) 29(5.715,1.45) 30(5.715,-1.45) 31(6.985,1.45) 32(6.985,-1.45) 33(8.255,1.45) 34(8.255,-1.45) 35(9.525,1.45) 36(9.525,-1.45) 37(10.795,1.45) 38(10.795,-1.45) 39(12.065,1.45) 40(12.065,-1.45)
  round 1.35 hole 1.35 unplated paste-5.563 mask-5.563: M1(13.652,0) M2(-13.652,0)
  silkscreen extent -14.29,-1.53 14.29,2.15, body extent -14.65,-1.58 14.65,2.25, height 4.57
TDFN8_M050_2.0X3.0_EP [mm] "TDFN8_M050_2.0x3.0_EP"
  rrect20% 0.75x0.3 smd mask+0.051: 1(-1.45,0.75) 2(-1.45,0.25) 3(-1.45,-0.25) 4(-1.45,-0.75) 5(1.45,-0.75) 6(1.45,-0.25) 7(1.45,0.25) 8(1.45,0.75)
  rect 1.75x1.45 smd mask+0.051: 9(0,0)
  silkscreen extent -1.5,-1 1.5,1, body extent -1.5,-1 1.5,1, height 1.01
TE_SMA_1814832_TH_VER [mm]
  round 2.286 hole 1.5: 1(0,0)
  round 2.54 hole 1.6: 2(-2.54,-2.54) 3(2.54,-2.54) 4(2.54,2.54) 5(-2.54,2.54)
  silkscreen extent -3.2,-3.2 3.2,3.2, body extent -3.2,-3.2 3.2,3.2, height 9.5
TOUCH_SLIDER2_28.0X7.0-4 [mm]
  round 1 smd paste-0.51 mask-0.51: 1(1.424,3.924) 2(11.4,4) 3(19.5,4) 4(27.6,4)
  Top Layer region: 28.5,7.5 26.5,7.5 20.4,6 20.4,5.8 26,4 20.4,2.2 20.4,2 26.5,0.5 28.5,0.5 28.5,2
  Top Layer region: 24,7.5 18.2,7.5 12.1,6 12.1,5.8 17.7,4 12.1,2.2 12.1,2 18.2,0.5 24,0.5 24,0.7 18.5,2 24.3,3.9 24.3,4.1 18.538,6 24,7.3
  Top Layer region: 15.7,7.5 9.9,7.5 3.8,6 3.8,5.8 9.4,4 3.8,2.2 3.8,2 9.9,0.5 15.7,0.5 15.7,0.7 10.2,2 16,3.9 16,4.1 10.238,6 15.7,7.3
  Top Layer region: 7.4,7.5 1.6,7.5 0.5,7.5 0.5,4 0.5,0.5 1.6,0.5 7.4,0.5 7.4,0.7 1.9,2 7.7,3.9 7.7,4.1 1.938,6 7.4,7.3
  silkscreen extent 0,0 29,8
TP_1.0_SMD [mm] "Test Point, 1.0 mm, SMD"
  round 1 smd paste-0.501: 1(0,0)
  silkscreen extent -0.5,-0.5 0.5,0.5
TP_INGUN_50_OHM_CLOSED [mm] "TP_INGUN_50_OHM_CLOSED"
  round 0.8 / inner round 0.508 / far side round 0.508 hole 0.25 mask+0: 1(0,0)
  round 0.5 smd paste-0.255 mask-0.41: 2(0,-1.15)
  Top Layer lines w0.7: 0,-1.15 cw(c0,0) -1.15,0 cw(c0,0) 0,-1.15
  silkscreen extent -1.5,-1.5 1.5,1.5
X_MCS_CM8V-T1A [mm] "Crystal MCS CM8V-T1A (2 pin)"
  rrect25% 0.8x1.5 smd paste-0.15 mask+0.051: 1(-0.75,0)
  rrect25% 0.85x1.5 smd paste-0.15 mask+0.051: 2(0.75,0)
  silkscreen extent -1,-0.6 1,0.6, body extent -1,-0.6 1,0.6, height 0.97
X_SSS_DSX211SH_2.05X1.65-4 [mm] "X_SSS_DSX211SH_2.05X1.65-4"
  rrect20% 0.9x0.8 smd mask+0.051: 1(-0.7,-0.55) 2(0.7,-0.55) 3(0.7,0.55) 4(-0.7,0.55)
  silkscreen extent -1.02,-0.82 1.02,0.82, body extent -1.07,-0.87 1.07,0.87, height 0.51

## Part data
AT1: library part ANT_INVERTED_F
C1 C2 C3 C4 C5 C6 C7 C8 C10 C102 C103 C106 C107 C111 C113 C114 C115 C116 C117 C124 C200 C201 C203 C207 C208: library part C0402
C110 C112: library part C0603
C205: library part C0805
L1 L2 L3 L4 L5 L6 L7: library part L0402
L100: library part LQH3NP
L102 L103: library part BLM18AG
P1: library part SMA_TH
P2: library part HIROSE_U.FL
R1 R2 R100 R103 R200 R201 R210 R211 R212 R213: library part R0402
T2: library part TOUCH_SLIDER
TP1: library part TP_RF
U100: library part MX25R8035
X1: library part DSX211SH
X2: library part CM8V-T1A

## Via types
v1: diameter 20, hole 9.84, Top Layer to Bottom Layer, tented both sides, 403 vias
v2: diameter 13/13 (per signal layer), hole 5.91, Top Layer to Signal Layer 2, tented both sides, 31 vias
v3: diameter 13/13 (per signal layer), hole 5.91, Top Layer to Signal Layer 2, tented top, 1 vias

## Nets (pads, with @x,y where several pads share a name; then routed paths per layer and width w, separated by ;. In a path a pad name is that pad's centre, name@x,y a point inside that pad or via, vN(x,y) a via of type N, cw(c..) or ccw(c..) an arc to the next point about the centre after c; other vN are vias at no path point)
3V3: C200.1 P200.1 R200.2 TPJ10.1 U200.1 U200.8 | length 1662.7
  PWR Layer 4 w12: v1(116.14,1374.02) 116.14,1376.53 190.4,1450.79 836.61,1450.79 907,1380.4 907,1189.45 v1(905.51,1190.94) 905.51,1176.12 989.49,1092.14 v1(992.5,1092.14) 998.37,1086.27 998.37,1013.84 ; v1(903,1014.22) 996.22,1014.22 997.49,1012.96 998.37,1013.84 ; v1(998.37,985.68) 998.37,1013.84
  Bottom Layer w10: P200.1@115.55,1320.87 115.55,1373.43 v1(116.14,1374.02)
  Bottom Layer w12: U200.8@901.27,1041.39 901.27,1012.96 902.54,1014.22 v1(903,1014.22) ; R200.2@968.5,996.06 987.98,996.06 v1(998.37,985.68) 998.37,911.75 TPJ10.1@1001.97,915.35 ; v1(992.5,1092.14) C200.1@992.5,1119.71
  Bottom Layer w12.01: U200.1@901.27,1155.56 901.51,1155.8 901.51,1186.95 v1(905.51,1190.94) ; U200.1@901.28,1156.1 901.33,1156.14 U200.1@901.33,1168.69
5V: P200.37 TPJ12.1 | length 85.2
  Bottom Layer w13: P200.37@1015.55,1320.87 1015.55,1244.29 TPJ12.1@1021.65,1238.19
BOARD_ID_SCL: P200.39 TPJ14.1 U200.6 | length 423.9
  Bottom Layer w4: U200.6@940.64,1041.39 940.64,1031.63 953.16,1019.11 1025.01,1019.11 TPJ14.1@1037.4,1031.5 1045.86,1039.96 1045.86,1104.18 1063.09,1121.4 1063.09,1144.5 1055.86,1151.72 1055.86,1311.18 P200.39@1065.55,1320.87
BOARD_ID_SDA: P200.40 TPJ15.1 U200.5 | length 489.3
  Bottom Layer w4: U200.5@960.33,1041.39 962.27,1039.44 U200.5@962.27,1028.74 ; U200.5@962.27,1028.29 U200.5@962.27,1028.74 ; P200.40@1065.55,1435.04 1065.55,1406.1 1040.35,1380.91 1040.35,1284.5 1047.34,1277.51 1047.34,1143.8 TPJ15.1@1037.4,1133.86 1037.4,1068.87 997.27,1028.74 U200.5@962.27,1028.74
BOARD_ID_WP: R200.1 TPJ16.1 U200.7 | length 563.8
  Signal Layer 5 w4: v1(962.22,616.12) 1022.17,616.12 1022.47,616.42 v1(1027.8,616.42)
  Bottom Layer w4: U200.7@925.07,1027.62 933.07,1019.62 933.07,996.06 942.98,996.06 942.98,974.12 976.28,940.82 976.28,904.72 1011,870 1011,633.22 v1(1027.8,616.42) ; TPJ16.1@954.72,580.71 962.22,588.21 v1(962.22,616.12)
GND: AT1.2 BAL1.5 C1.1 C2.1 C6.2 C7.2 C8.2 C10.2 C102.2 C103.2 C106.2 C107.2 C110.2 C111.2 C112.2 C113.2 C114.2 C115.2 C116.2 C117.2 C124.2 C200.2 C201.2 C203.2 C205.2 C207.2 C208.2 P1.2 P1.3 P1.4 P1.5 P2.2 P2.3 P200.2 P200.38 P201.1 P201.39 SH100.1 TP1.2 TPJ13.1 U1.A13 U1.B11 U1.B12 U1.E5 U1.E6 U1.E7 U1.E8 U1.E9 U1.F5 U1.F6 U1.F7 U1.F8 U1.F9 U1.G5 U1.G6 U1.G7 U1.G8 U1.G9 U1.H5 U1.H6 U1.H7 U1.H8 U1.H9 U1.J5 U1.J6 U1.J7 U1.J8 U1.J9 U1.K2 U1.L2 U1.M2 U1.M3 U1.M4 U1.M5 U1.M6 U1.M7 U1.N5 U1.N6 U100.B2 U200.2 U200.3 U200.4 X1.2 X1.4 | length 7957.8
  Top Layer w5: 171.5,979.06 171.5,965.39 175.5,961.39 175.5,959.39 164.5,948.39 164.5,899.06 174.5,889.06 174.5,883.64 184.1,874.04 184.1,861.61 258.26,861.61 ; v1@236.84,1014.22 v1(239,1014.22) ; C1.1@368.11,1145.67 C1.1@370.08,1145.67 ; X1.4@606.3,968.5 638.32,936.48 683.19,936.48
  Top Layer w7.99: C124.2@531.94,661.05 548.78,677.89 548.78,710.71 U100.B2@549.51,711.44
  Top Layer w8: v1(309.07,783.29) 309.07,791.36 U1.A13@318.9,801.18 U1.B12@338.58,820.87 U1.B11@358.27,820.87 ; v1(367.13,1168.31) v1(367.13,1195.87) ; v1(407.48,865.16) v1@407.48,870.08 ; v1(465.46,975.11) 469.19,975.11 470.63,973.67 466,969.04 v1@466.54,968.5 ; U1.E5@476.38,879.92 466.54,889.76 ; v1(505.86,974.26) 519.84,974.26 525.59,968.5 U1.K2@535.43,978.35 U1.L2@535.43,998.03 ; U1.E9@397.64,879.92 392.72,879.92 v1(382.87,889.76) 387.8,889.76 U1.F9@397.64,899.61 ; U1.E9@397.64,879.92 407.48,889.76 ; U1.E9@397.64,879.92 v1@407.48,870.08 ; U1.F9@397.64,899.61 407.48,889.76 ; U1.F9@397.64,899.61 407.48,909.45 ; v1@407.48,870.08 U1.E8@417.32,879.92 ; 407.48,889.76 U1.E8@417.32,879.92 ; 407.48,889.76 U1.F8@417.32,899.61 ; 407.48,909.45 U1.G9@397.64,919.29 407.48,929.13 ; 407.48,909.45 U1.F8@417.32,899.61 ; 407.48,909.45 U1.G8@417.32,919.29 ; 407.48,929.13 U1.H9@397.64,938.98 407.48,948.82 ; 407.48,929.13 U1.G8@417.32,919.29 ; 407.48,929.13 U1.H8@417.32,938.98 ; 407.48,948.82 U1.J8@417.32,958.66 ; 407.48,948.82 U1.J9@397.64,958.66 397.64,963.58 v1(407.48,973.43) 417.32,963.58 U1.J8@417.32,958.66 ; 407.48,948.82 U1.H8@417.32,938.98 ; U1.E8@417.32,879.92 427.17,889.76 ; U1.E8@417.32,879.92 432.09,865.16 433.83,866.91 435.01,865.73 v1(437.84,865.73) ; U1.F8@417.32,899.61 427.17,889.76 ; U1.F8@417.32,899.61 427.17,909.45 ; U1.G8@417.32,919.29 427.17,909.45 ; U1.G8@417.32,919.29 427.17,929.13 ; U1.H8@417.32,938.98 427.17,929.13 ; U1.H8@417.32,938.98 427.17,948.82 ; U1.J8@417.32,958.66 427.17,948.82 ; 427.17,889.76 U1.E7@437.01,879.92 ; 427.17,889.76 U1.F7@437.01,899.61 ; 427.17,909.45 U1.F7@437.01,899.61 ; 427.17,909.45 U1.G7@437.01,919.29 ; 427.17,929.13 U1.G7@437.01,919.29 ; 427.17,929.13 U1.H7@437.01,938.98 ; 427.17,948.82 U1.H7@437.01,938.98 ; 427.17,948.82 U1.J7@437.01,958.66 446.85,948.82 ; U1.E7@437.01,879.92 437.84,879.09 v1(437.84,865.73) ; U1.E7@437.01,879.92 446.85,889.76 ; U1.F7@437.01,899.61 446.85,889.76 ; U1.F7@437.01,899.61 446.85,909.45 ; U1.G7@437.01,919.29 446.85,909.45 ; U1.G7@437.01,919.29 446.85,929.13 ; U1.H7@437.01,938.98 446.85,929.13 ; U1.H7@437.01,938.98 446.85,948.82 ; v1(437.84,865.73) 439,865.73 440.18,866.91 441.93,865.16 U1.E6@456.69,879.92 ; 446.85,889.76 U1.E6@456.69,879.92 ; 446.85,889.76 U1.F6@456.69,899.61 ; 446.85,909.45 U1.F6@456.69,899.61 ; 446.85,909.45 U1.G6@456.69,919.29 ; 446.85,929.13 U1.G6@456.69,919.29 ; 446.85,929.13 U1.H6@456.69,938.98 ; 446.85,948.82 U1.H6@456.69,938.98 ; 446.85,948.82 U1.J6@456.69,958.66 ; U1.E6@456.69,879.92 466.54,889.76 ; U1.F6@456.69,899.61 466.54,889.76 ; U1.F6@456.69,899.61 466.54,909.45 ; U1.G6@456.69,919.29 466.54,909.45 ; U1.G6@456.69,919.29 466.54,929.13 ; U1.H6@456.69,938.98 466.54,929.13 ; U1.H6@456.69,938.98 466.54,948.82 ; U1.J6@456.69,958.66 v1@466.54,968.5 ; U1.J6@456.69,958.66 466.54,948.82 ; U1.M6@456.69,1017.72 456.69,997.91 453.04,994.26 452.33,994.97 v1(452.33,996.68) 452.33,995.97 450.62,994.26 437.01,1007.87 U1.M7@437.01,1017.72 U1.M6@456.69,1017.72 ; U1.M6@456.69,1017.72 U1.N6@456.69,1037.4 456.69,1045.28 467.06,1055.65 v1(468.4,1055.65) 468.4,1053.25 476.38,1045.28 U1.N5@476.38,1037.4 U1.M5@476.38,1017.72 ; U1.M6@456.69,1017.72 U1.M5@476.38,1017.72 ; 466.54,889.76 U1.F5@476.38,899.61 ; 466.54,909.45 U1.F5@476.38,899.61 ; 466.54,909.45 U1.G5@476.38,919.29 ; 466.54,929.13 U1.G5@476.38,919.29 ; 466.54,929.13 U1.H5@476.38,938.98 ; 466.54,948.82 U1.H5@476.38,938.98 ; 466.54,948.82 U1.J5@476.38,958.66 v1@466.54,968.5 ; U1.F5@476.38,899.61 491.14,914.37 492.7,912.8 491,911.1 v1(491,909.22) ; U1.G5@476.38,919.29 483.49,912.18 485.52,914.22 490.52,909.22 v1(491,909.22) ; U1.H5@476.38,938.98 494.12,921.23 491,918.1 492.7,916.4 491,914.7 v1(491,909.22) ; U1.M5@476.38,1017.72 476.38,1007.87 487.37,996.88 487,996.5 v1(487,991.22) 487,998.81 496.06,1007.87 U1.M4@496.06,1017.72 ; U1.M5@476.38,1017.72 U1.M4@496.06,1017.72 ; U1.M4@496.06,1017.72 U1.M3@515.75,1017.72 ; U1.M3@515.75,1017.72 512.02,1013.99 v1(512.02,996.22) 533.62,996.22 U1.L2@535.43,998.03 ; U1.M3@515.75,1017.72 U1.M2@535.43,1017.72 U1.L2@535.43,998.03
  Top Layer w10: v1@238.13,1013.84 C208.2@258.61,1013.84 ; SH100.1@360.83,484.06 SH100.1@384.1,484.06 ; SH100.1@562.7,472.13 559,475.83 SH100.1@567.22,484.06 ; v1(577,975.96) 580.71,972.25 580.71,972.44 602.36,972.44 X1.4@606.3,968.5 ; SH100.1@589.09,476.1 SH100.1@597.05,484.06
  Top Layer w12: v1(39.29,1074.8) v1@39.29,1076.77 ; v1(193.34,683.89) 196.42,683.89 C115.2@213.97,666.34 ; v1(204.76,779.73) 218.09,779.73 C112.2@230.78,792.43 ; C115.2@211.02,666.34 211.34,666.02 234.91,666.02 257.02,688.13 v1(308.81,688.13) ; 232.28,754.77 C112.2@232.28,783.46 ; C112.2@232.28,790.9 232.28,787.5 C113.2@269.69,787.5 ; C113.2@271.21,787.4 C113.2@273.62,787.4 305.12,787.4 309.07,783.45 v1(309.07,783.29) ; v1(373.38,625.16) 373.38,628.24 371.75,629.88 374.09,632.22 380.2,626.11 385.26,631.16 386.1,630.33 387,631.24 384.74,633.5 385.46,634.22 385.83,633.86 383.86,631.89 C110.2@383.86,663.39 ; C111.2@381.89,718.5 383.86,716.54 381,713.68 v1@397,697.68 ; v1(397,695.22) 411.42,709.64 C116.2@411.42,710.14 ; v1(407.5,1264.81) 407.5,1290.35 ; 407.48,1290.37 407.48,1311.02 C10.2@435.04,1311.02 435.04,1342.77 448.21,1355.95 473.4,1355.95 C6.2@473.4,1365.18 ; C2.1@409.45,1248.03 v1@431.1,1226.38 ; C116.2@411.42,718.5 C116.2@411.42,710.14 ; v1(431.1,1188.97) v1@431.1,1187.01 ; v1@431.1,1189.54 v1@431.1,1187.01 ; v1(431.12,1229.38) 428.1,1229.38 v1@431.1,1226.37 ; C117.2@440.95,718.5 C117.2@440.95,709.33 ; C117.2@441.01,709.39 C117.2@440.95,709.33 ; v1(468.4,1055.65) 468.4,1063.1 455.23,1076.26 v1(455.23,1076.36) 455.13,1076.36 447.83,1083.66 v1(447.83,1101.38) 438.98,1110.24 438.98,1130.71 431.1,1138.59 v1(431.1,1152.69) v1@431.1,1187.01 ; v1(482.07,1381.59) 482.07,1363.96 C6.2@478.35,1360.24 483.38,1355.21 630.41,1355.21 652.08,1376.87 648.6,1380.35 v1(622.43,1380.35) ; BAL1.5@538.41,1265.75 570.94,1265.75 570.01,1264.81 v1(567.94,1264.81) ; v1@599.54,1263.58 594.49,1268.62 C7.2@594.49,1289.37 622.05,1289.37 622.05,1270.85 v1@624.94,1267.96 ; C102.2@627.95,883.86 C102.2@627.95,885.83 ; C207.2@644.4,1057.35 645.84,1055.91 v1(676.48,1055.91) ; X1.2@659.17,1021.77 665.29,1027.89 v1(682.53,1027.89) ; v1@675.6,1264.45 678.38,1267.22 v1(675,1267.22) 675,1290.19 695.46,1290.19 C8.2@697.54,1288.11 ; v1@705.77,1268.45 v1(707,1267.22) v1@709.46,1267.22 ; v1@706.79,1263.23 v1@708,1264.44 ; v1@707.56,1268.35 706.15,1268.35 700.78,1273.72 700.78,1285.44 C8.2@696.85,1289.37 751.76,1289.37 v1@779.7,1261.43 ; SH100.1@1102.36,1454.72 v1(1102.36,1456.69) ; C116.2@411.42,710.14 v1(426.51,695.04) 426.66,695.04 C117.2@440.95,709.33 ; v1@431.1,1187.01 v1@431.1,1226.37
  Top Layer w12.01: v1@531.94,636.9 C124.2@531.94,661.05 ; 646.52,804.47 636.26,814.73 C114.2@636.26,825.66 657.91,825.66 679.1,804.47 689.15,804.47 703.77,819.09 v1(703.77,851.42)
  Top Layer w17.99: C114.2@635.23,825.66 v1(635.23,866.03)
  Top Layer w20: v1(266.65,1106.57) C106.2@289.09,1106.57 289.09,1119.5 ; v1(345.49,1154.59) 348.43,1157.48 v1@352.36,1153.54 ; v1(356.3,1120.08) 361.22,1115.16 C107.2@377.95,1115.16 ; C1.1@368.11,1145.67 C1.1@367.13,1146.65 ; v1@352.36,1153.54 v1(367.13,1168.31) 367.13,1147.64 368.11,1146.65 C1.1@367.13,1146.65 ; v1@352.36,1153.54 360.24,1153.54 C1.1@367.13,1146.65
  Top Layer w25: v1(78.74,1584.65) 58.07,1584.65 ; v1@86.54,1336.61 P2.2@166.34,1336.61 189.16,1336.61 216,1363.45 v1(216,1375.22) ; 98.82,1218.5 P2.3@166.34,1218.5 v1(222.44,1218.5) ; 58.07,1584.65 v1(43.31,1584.65) 43.31,1617.79 AT1.2@51.11,1625.59 58.07,1618.63 58.07,1584.65
  Top Layer w39.37: SH100.1@78.52,766.31 78.52,484.12 SH100.1@78.56,484.07 ; SH100.1@78.98,1508.07 v1(78.56,1507.66) v1(159.45,1507.66) ; SH100.1@90.55,496.06 SH100.1@78.56,484.07 ; v1(322.83,1507.87) 323.03,1508.07 SH100.1@360.83,1508.07 SH100.1@411.22,1508.07 ; SH100.1@360.83,484.06 SH100.1@78.56,484.07 ; SH100.1@384.1,484.06 516.12,484.06 518.03,485.97 565.31,485.97 567.22,484.06 SH100.1@597.05,484.06 SH100.1@827.56,484.06 ; v1(411.42,1507.87) SH100.1@411.22,1508.07 ; v1(549.21,1507.87) SH100.1@549.41,1508.07 ; SH100.1@760.8,1507.87 597.24,1507.87 SH100.1@597.05,1508.07 SH100.1@549.41,1508.07 ; SH100.1@764.86,1507.87 833.07,1507.87 v1(833.27,1508.07) SH100.1@833.68,1507.66 ; SH100.1@833.27,484.06 SH100.1@1102.13,484.06 ; SH100.1@1015.75,1507.87 1015.96,1507.66 v1(1072.83,1507.66) SH100.1@1102.15,1507.66 ; SH100.1@1102.15,484.07 1102.15,1238.37 SH100.1@1102.56,1238.78 ; SH100.1@411.22,1508.07 SH100.1@549.41,1508.07
  Signal Layer 2 w12: v1(567.94,1264.81) 570.01,1264.81 570.94,1265.75 v1@571.93,1264.76
  Bottom Layer w10: C205.2@172.76,606.81 193.43,606.81 C205.2@194.41,607.8 ; v1(931.5,1185.5) 941.12,1175.87 U200.3@941.12,1155.51 ; TP1.2@938.78,1495.47 TP1.2@939.12,1495.13 ; 943.57,1479.98 943.57,1490.69 TP1.2@940.94,1493.31 ; U200.4@960.33,1155.51 992.13,1155.51 992.13,1182.94 v1(992.31,1183.13) ; TP1.2@939.12,1495.13 939.12,1473.28 940.94,1471.46 TP1.2@940.94,1493.31 ; TP1.2@939.12,1495.13 TP1.2@940.94,1493.31
  Bottom Layer w12: U200.2@920.96,1155.56 920.96,1174.95 v1(931.5,1185.5) ; TPJ13.1@968.5,755.91 968.5,748.65 976.9,757.04 v1(976.9,788.11) ; 984.06,1540.75 990.55,1547.24 v1(1012.8,1547.24)
  Bottom Layer w12.01: 141.48,531.31 141.48,538.12 C201.2@151.57,548.21
  Bottom Layer w20: C201.2@151.57,551.64 v1(174.72,551.64) ; C203.2@151.57,579.99 174.75,579.99 v1(174.99,579.75)
  Bottom Layer w25: P201.1@114.17,364.17 116.14,362.2 88.58,362.2 88.58,385.83 105.71,385.83 P201.1@115.55,375.98 ; P200.2@115.55,1435.04 115.55,1532.87 v1(127.95,1545.28) ; v1(160.74,624.41) 161.19,624.41 161.44,624.16 191.28,624.16 C205.2@191.28,618.42 ; C205.2@185.04,625 C205.2@185.04,630.45 ; v1(1015.75,1379.92) 1015.75,1434.84 P200.38@1015.55,1435.04 1015.55,1507.46 v1(1016.73,1508.64) ; P201.39@1065.55,375.98 1065.55,355.71 1068.9,352.36 1070.87,354.33 v1(1094.49,354.33) v1(1094.49,379.92) ; P201.39@1065.55,375.98 1090.55,375.98 v1(1094.49,379.92) ; P201.39@1065.55,375.98 1069.49,379.92 v1(1094.49,379.92)
  other v1: 40.35,349.41 1139.76,349.41 88.58,361.07 1139.69,377.95 39.29,385.83 88.58,386.67 841.18,429.82 791.78,431.98 935.29,432.76 988.17,432.37 118.11,433.07 331.4,433.01 415.4,433.04 580.63,433.74 636.64,432.84 882.82,432.89 1043.31,433.07 39.29,482.28 1139.69,488.19 1139.69,539.37 644.86,541.4 606.77,543.86 39.29,545.28 1043.31,551.18 336.27,569.42 385.89,568.82 780.94,584.61 1139.69,584.65 846.46,600.39 39.29,602.36 1139.69,625.98 451.3,627.67 536.39,629.23 1043.31,639.76 39.29,665.35 1139.69,665.35 729.69,669.41 1139.69,710.63 682.97,715.04 39.29,718.5 1043.31,718.5 513.86,751.74 1139.69,753.94 39.29,769.69 1139.69,797.24 39.46,815.4 1139.69,836.61 738.19,846.46 779.88,846.57 866.14,846.46 974.41,846.46 609.28,870.12 1139.69,879.92 698.65,893.15 738.1,893.15 780.13,893.4 860.99,892.94 190.15,914.22 1139.69,921.26 39.37,935.04 1043.31,935.04 728.39,951.6 1139.69,962.6 189.21,994.24 39.37,1003.94 1139.69,1005.91 130.81,1015.86 189.21,1041.2 1139.69,1047.24 1139.69,1090.55 134.61,1095.35 606.3,1111.88 39.29,1124.02 164.86,1126.15 1139.69,1133.86 606.44,1144.48 39.29,1173.23 660.55,1177.99 1139.69,1179.13 251.51,1180.43 107.75,1188.4 39.29,1220.47 1139.69,1222.44 263.78,1228.34 305.12,1228.35 338.58,1228.35 840.28,1260.49 984.25,1259.84 779.24,1262.22 602.4,1264.09 39.29,1265.75 625.37,1267.19 1139.69,1267.72 39.29,1318.9 1139.69,1320.87 84.61,1338.54 1094.49,1342.52 442.04,1370.03 530.12,1374.14 267.72,1377.95 663.75,1378.3 711.9,1378.42 762.8,1377.95 814.96,1377.95 864.17,1377.95 972.44,1377.95 1064.96,1377.95 341.28,1387.26 1141.73,1433.07 39.37,1435.04 39.37,1472.44 1141.73,1472.44 39.37,1505.91 478.35,1507.87 762.83,1509.9 1141.73,1509.84 39.37,1543.31 78.74,1545.27 179.13,1545.28 279.53,1545.27 322.83,1545.27 367.13,1545.27 411.42,1545.27 454.72,1545.27 501.97,1545.27 544.29,1545.28 588.58,1545.27 625,1545.27 667.32,1545.27 706.69,1545.27 750,1545.27 789.37,1545.27 827.76,1545.28 864.17,1546.26 1047.24,1547.24 1082.68,1547.24 1114.17,1547.24 1141.73,1547.24 842.52,1583.66 879.92,1583.66 111.22,1583.99 153.54,1583.99 257.87,1583.99 299.21,1583.99 343.5,1583.99 386.81,1583.99 432.09,1583.99 478.35,1583.99 519.69,1583.99 565.94,1583.99 606.3,1583.99 643.7,1583.99 684.06,1583.99 727.36,1583.99 766.73,1583.99 806.1,1583.99 1029.53,1584.65 1064.96,1584.65 1096.46,1584.65 1127.95,1584.65
NetAT1_1: AT1.1 R1.2 | length 374.5
  Top Layer w18: AT1.1@204.1,1625.59 204.1,1596.07 ccw(c265.83,1596.07) 222.18,1552.42 224.61,1550 cw(c177.56,1502.95) 244.09,1502.95 244.09,1474.29 ; 243.17,1474.29 ccw(c316.06,1474.29) 264.52,1422.74 291.34,1395.92 R1.2@374.02,1313.25
NetBAL1_1: BAL1.1 C6.1 L6.2 | length 67
  Top Layer w8: C6.1@477.36,1320.87 C6.1@478.35,1321.85
  Top Layer w15.6: BAL1.1@473.41,1291.34 477.36,1295.3 C6.1@477.36,1320.87 ; C6.1@478.35,1324.8 L6.2@512.8,1324.8
NetBAL1_3: BAL1.3 C5.2 L4.1 | length 88.9
  Top Layer w8: L4.1@460.63,1184.06 473.43,1196.85 482.28,1196.85 C5.2@488.19,1202.76 488.19,1239.17 489.17,1240.16 BAL1.3@473.41,1240.16
NetBAL1_4: BAL1.4 C5.1 L3.1 | length 88.1
  Top Layer w8: BAL1.4@538.41,1240.16 523.62,1240.16 C5.1@523.62,1202.76 528.54,1197.83 538.39,1197.83 551.18,1185.04 L3.1@551.18,1184.06
NetC1_2: C1.2 L1.2 L2.1 | length 66.8
  Top Layer w15.6: C1.2@399.61,1146.65 L2.1@399.61,1176.18 ; C1.2@403.54,1145.67 407.48,1141.73 407.48,1126.97 L1.2@416.34,1118.11 ; C1.2@403.54,1146.65 C1.2@406.64,1143.55
NetC2_2: C2.2 L2.2 R1.1 R2.1 | length 74.3
  Top Layer w15.6: R1.1@374.02,1279.53 374.02,1248.03 374.02,1240.16 396.65,1217.52 L2.2@399.61,1217.52
NetC3_1: C3.1 L3.2 U1.N1 | length 211.2
  Top Layer w8: v1(521.65,1177.17) C3.1@521.65,1154.53 529.53,1146.65 547.24,1146.65 L3.2@551.18,1142.72 ; U1.N1@555.12,1037.4 555.12,1062.01 v1(566.93,1073.82)
  PWR Layer 4 w8: v1(521.65,1177.17) v1(566.93,1073.82)
NetC3_2: C3.2 L5.2 U1.N3 | length 94.4
  Top Layer w5: U1.N3@515.75,1037.4 510.97,1042.18 510.97,1072.98 L5.2@526.57,1088.58 ; C3.2@521.65,1119.09 521.65,1095.47 528.54,1088.58 L5.2@527.56,1087.6
NetC4_1: C4.1 L4.2 U1.N2 | length 206.1
  Top Layer w8: L4.2@460.63,1142.72 464.57,1146.65 483.27,1146.65 C4.1@491.14,1154.53 v1(491.14,1177.17) ; U1.N2@535.43,1037.4 v1(535.43,1062.99)
  PWR Layer 4 w8: v1(491.14,1177.17) v1(535.43,1062.99)
NetC4_2: C4.2 L5.1 U1.N4 | length 92.7
  Top Layer w5: L5.1@485.24,1088.58 501.97,1071.85 501.97,1043.31 U1.N4@496.06,1037.4 ; L5.1@487.2,1088.58 491.14,1092.52 C4.2@491.14,1119.09
NetC7_1: C7.1 L6.1 L7.2 | length 70.9
  Top Layer w15.6: L6.1@554.13,1324.8 C7.1@594.49,1324.8 L7.2@625,1324.8
NetC8_1: C8.1 L7.1 P1.1 TP1.1 | length 691.5
  Top Layer w18: L7.1@666.34,1324.8 C8.1@696.85,1324.8 699.12,1327.07 856,1327.07 ccw(c857.18,1408.67) 938.78,1407.48 TP1.1@938.78,1540.75 978.58,1580.55 ccw(c907.87,1651.26) 1007.87,1651.26 P1.1@1007.87,1755.9
NetC102_1: C102.1 C103.1 L102.2 U1.J1 U1.J2 | length 155.9
  Top Layer w10: U1.J2@535.43,958.66 U1.J1@555.12,958.66 560.34,953.44 565.38,953.44 570.87,953.44 573.86,953.44 585.11,942.2 585.11,938.78 598.43,925.46 C103.1@598.43,921.26
  Top Layer w12: C103.1@598.43,921.26 657.48,921.26 L102.2@667.32,911.42
NetC112_1: C112.1 C113.1 R100.2 U1.B13 | length 136.8
  Top Layer w10: C113.1@275.59,820.87 286.15,810.31 308.06,810.31 318.62,820.87 U1.B13@318.9,820.87
  Top Layer w15: C112.1@232.28,838.58 243.25,827.62 273.62,827.62 C113.1@273.62,822.83 C113.1@275.59,820.87
  Top Layer w20: R100.2@188.18,839.83 C112.1@219.52,839.83
NetC117_1: C117.1 U1.A9 | length 68.9
  Top Layer w8: U1.A9@397.64,797.24 U1.A9@397.64,797.97 ; U1.A9@397.64,801.18 U1.A9@397.64,797.97 ; 404.64,790.96 U1.A9@397.64,797.97
  Top Layer w12: 404.64,790.96 413.62,781.98 418.8,781.98 440.95,759.84 C117.1@440.95,753.94
NetL1_1: L1.1 U1.N7 | length 47.5
  Top Layer w8: U1.N7@437.01,1037.4 437.01,1052.17
  Top Layer w15.6: L1.1@416.34,1076.77 434.22,1058.89 cw(c427.5,1052.17) 437.01,1052.17
NetL100_1: L100.1 U1.A12 | length 89.2
  Top Layer w8: 338.58,785.43 U1.A12@338.58,801.18
  Top Layer w10: L100.1@299.21,742.13 322.83,742.13 L100.1@338.58,757.87
  Top Layer w25: L100.1@338.58,757.87 338.58,785.43
NetL101_2: L101.2 R100.1 | length 65
  Top Layer w20: L101.2@129.37,823.71 138.64,814.44 170.27,814.44 179.89,804.82 R100.1@186.5,804.82
NetP2_1: P2.1 R2.2 | length 109.7
  Top Layer w15.6: P2.1@229.33,1277.56 P2.1@230.32,1278.54
  Top Layer w15.75: P2.1@230.32,1278.54 R2.2@338.58,1278.54
NetU1_K1: U1.K1 X1.1 | length 122.7
  Top Layer w4: U1.K1@555.12,978.35 555.12,980.97 566.11,991.96 627.89,991.96 X1.1@656.19,963.67 ; X1.1@647.64,966.54 X1.1@649.61,964.57
NetU1_L1: U1.L1 X1.3 | length 78.6
  Top Layer w4: U1.L1@555.12,998.03 556.71,996.44 559.28,996.44 565.88,1003.05 607.61,1003.05 612.88,1008.32 X1.3@612.88,1018.79 ; X1.3@606.3,1018.79 X1.3@606.3,1023.62
PAVDD: L103.1 R210.1 R211.1 | length 536.2
  Top Layer w25: v1(198.97,1118.8) 198.82,1118.95 v1(198.82,1144.69) 199.79,1145.66 254.91,1145.66 L103.1@255.91,1146.65
  PWR Layer 4 w25: v1@174.18,769.77 162.35,781.6 162.35,1068.06 198.97,1104.68 v1(198.97,1118.8) 198.82,1118.95 v1(198.82,1144.69) v1@199,1144.5
  Bottom Layer w25: v1(161.14,787.69) 161.14,781.37 177.2,765.31 177.41,765.51 175.62,767.29 v1(175.62,767.75) 176.44,767.75 183.39,760.8 R210.1@183.39,746.68
RADIO_PA0: P200.19 P201.36 TPJ5.1 U1.M13 | length 2389.4
  Top Layer w4: v1@280.93,1017.72 U1.M13@318.9,1017.72
  Signal Layer 5 w4: v1(283,1015.22) 283,996.54 296.88,982.66 311.16,982.66 341.71,1013.22 403.96,1013.22 413.33,1003.84 413.33,990.59 413.19,990.45 413.19,990.34 423.48,980.05 423.48,968.8 450.14,942.15 588.44,942.15 639.37,993.08 639.37,1116.81 655.82,1133.26 v1(667.13,1133.26) 669.42,1130.97 723.6,1130.97 736.35,1118.22 845.57,1118.22 v1@863.19,1100.6 ; v1(586.65,1379.51) 604.21,1361.95 801.22,1361.95 903.96,1259.22 v1(927,1259.22)
  Bottom Layer w4: P200.19@565.55,1328.71 565.55,1343.79 578.36,1356.6 578.36,1375.6 582.27,1379.51 v1(586.65,1379.51) ; TPJ5.1@612.2,1011.81 615.22,1014.82 615.22,1056.25 624.9,1065.93 662.34,1065.93 674.9,1078.48 674.9,1125.5 v1(667.13,1133.26) ; 856,1082.9 856,998.98 900.73,954.25 917.6,954.25 943,928.85 943,766.73 942.82,766.54 942.82,745.27 962,726.09 962,638.52 928.25,604.77 928.25,564.14 953.22,539.17 953.22,502.48 P201.36@965.55,490.16 ; 856.2,1082.9 864.41,1091.11 v1(864.41,1101.64) ; v1@866.61,1100.14 856,1110.74 856,1203.41 911.81,1259.22 v1(927,1259.22)
RADIO_PA1: P200.20 P201.37 TPJ6.1 U1.L13 | length 2268.1
  Top Layer w4: v1(303,999.22) 315.74,999.22 317.91,997.05 U1.L13@318.9,998.03
  Signal Layer 5 w4: v1(303,999.22) 305.32,999.22 327.32,1021.22 407.27,1021.22 421.33,1007.16 421.33,993.52 431.48,983.37 431.48,972.12 453.45,950.15 585.13,950.15 631.37,996.39 631.37,1120.13 660.51,1149.26 679.55,1149.26 689.38,1139.42 v1(739.94,1139.42) 739.94,1143.35 741,1144.41 759.19,1126.22 880,1126.22 v1(883,1129.22) ; v1(561.02,1377.95) 561.02,1370.86 577.93,1353.95 797.91,1353.95 874.83,1277.03 874.83,1216.98 884.59,1207.22 v1(885,1207.22)
  Bottom Layer w4: v1(561.02,1377.95) 561.02,1430.51 P200.20@565.55,1435.04 ; v1(739.94,1139.42) 739.94,1114 TPJ6.1@748.82,1105.12 ; v1@882.94,1129.22 882.94,1168.98 889.51,1175.55 889.51,1207.65 v1@884.84,1202.98 ; v1(885,1207.22) 885,1205.58 v1@886.22,1204.36 ; v1@889.28,1122.94 889.28,1092.13 872,1074.85 872,1005.61 907.36,970.25 924.22,970.25 960.28,934.19 960.28,896.04 995,861.32 995,532.77 ; 994.98,532.75 994.98,449.04 1015.55,428.47 P201.37@1015.55,375.98
RADIO_PA2: P200.21 P201.38 TPJ7.1 U1.L12 | length 1555.9
  Top Layer w4: U1.L12@338.58,998.03 349.21,998.03 v1(358.88,988.36)
  Signal Layer 5 w4: v1(358.88,988.36) 358.88,976.76 378.21,957.43 423.55,957.43 446.82,934.15 591.76,934.15 647.37,989.77 647.37,1001.25 ; v1@657.2,1085.91 v1(657.2,1083.41) 647.37,1073.59 647.37,1001.25 ; v1(911.39,989.73) 903.56,989.73 890.51,1002.77 648.89,1002.77 647.37,1001.25
  Bottom Layer w4: P200.21@615.55,1320.87 615.55,1287.41 619.47,1283.49 633.75,1283.49 641.86,1275.38 641.86,1246.71 628,1232.85 628,1219.35 639.86,1207.49 639.86,1186.21 631.53,1177.88 631.53,1121.23 TPJ7.1@649.21,1103.54 TPJ7.1@661,1115.33 ; v1(911.39,989.73) 922.87,978.25 927.54,978.25 968.28,937.51 968.28,901.4 1003,866.68 1003,514.77 1003.51,514.26 1003.51,502.2 1004.2,502.2 1008.88,497.52 1008.88,496.83 P201.38@1015.55,490.16
RADIO_PA3: P200.3 P200.22 TPJ8.1 U1.K13 | length 1403.6
  Top Layer w4: v1@273.62,978.35 U1.K13@318.9,978.35
  Signal Layer 2 w4: v1(113.72,997.08) 116.85,997.08 138.71,975.22 260,975.22 268,983.22 v1(273,983.22)
  Signal Layer 5 w4: v1(181.58,1376.79) 191.8,1376.79 209.37,1359.22 383.75,1359.22 417.38,1325.59 472.69,1325.59 500.33,1297.95 571.59,1297.95 583.94,1285.6 583.94,1272.56 583.94,1271.44 583.94,1248.95 v1@602.67,1230.22 ; v1(599,1230.22) v1@602.67,1230.22 ; v1@604.55,1232.1 v1@602.67,1230.22
  Bottom Layer w4: v1(113.72,997.08) 104.82,1005.98 104.82,1033.01 80.09,1057.73 80.09,1201.37 152.12,1273.4 152.12,1282.41 165.55,1295.85 P200.3@165.55,1320.87 165.55,1347.45 181.58,1363.48 v1(181.58,1376.79) ; TPJ8.1@614.17,1196.85 599,1212.02 v1(599,1230.22) 602.08,1230.22 586.12,1246.18 586.12,1271.56 592.15,1277.59 592.15,1359.12 602.97,1369.95 602.97,1397.54 P200.22@615.55,1410.11
RADIO_PA4: R103.2 U1.K12 U100.A3 | length 715.7
  Top Layer w4: v1(467.54,689.99) 490.84,689.99 504.24,703.4 535.57,703.4 U100.A3@535.74,703.57
  Signal Layer 2 w4: v1(215,992.22) 254.37,992.22 261.37,999.22 279.63,999.22 296.19,982.66 334.27,982.66 v2(338.58,978.35)
  Signal Layer 5 w4: v1(215,992.22) 216,991.22 216,963.44 236,943.44 236,843.24 270.91,808.33 441.49,808.33 457.45,792.38 457.45,719.83 467.54,709.73 v1(467.54,689.99)
RADIO_PA5: P200.18 U1.J13 | length 1082.6
  Top Layer w4: v1@305.62,958.59 305.7,958.66 U1.J13@318.9,958.66 U1.J13@318.18,957.94
  Signal Layer 2 w4: v1(112.23,965.08) 112.23,965.46 118.46,959.22 v1@302.59,959.22
  Signal Layer 5 w4: v1(157,1381.22) 157,1383.09 171.92,1398.02 248.52,1398.02 269.82,1419.32 454.69,1419.32 474.04,1399.97 474.04,1398.02 529.1,1398.02 v1(534.82,1403.73)
  Bottom Layer w4: v1(112.23,965.08) 96.82,980.49 96.82,1029.69 72.09,1054.42 72.09,1204.69 144.12,1276.72 144.12,1368.34 v1(157,1381.22)
  other v1: 304.58,958.51
RADIO_PA6: P201.4 U1.J12 | length 946.2
  Signal Layer 2 w4: v1(59.19,904.23) 89.11,934.15 89.11,966.46 103.73,981.08 107.09,981.08 119.56,981.08 133.42,967.22 280.63,967.22 288.07,974.66 322.58,974.66 v2(338.58,958.66)
  Signal Layer 5 w4: v1@56.64,897.49 48.47,889.32 48.47,845.89 64.07,830.3 64.07,537.84 152.87,449.04 168.44,449.04 178.37,439.12 v1(178.37,429.35)
  Bottom Layer w4: P201.4@165.55,490.16 178.37,477.34 v1(178.37,429.35)
RADIO_PA7: P201.6 U1.J11 | length 1023.7
  Top Layer w4: U1.J11@358.27,958.66 375.98,976.38 v1(381.89,976.38)
  Signal Layer 5 w4: v1@199.18,534.82 273.16,460.84 289.53,460.84 296.14,454.22 443,454.22 v1(464,433.22)
  Bottom Layer w4: v1(203.75,539.4) 203.75,524.17 215.55,512.37 P201.6@215.55,490.16 ; v1(381.89,976.38) 373.03,976.38 335.51,938.85 335.51,869.25 349.07,855.68 349.07,766.72 337.46,755.11 337.46,720.22 338.29,719.39 426.81,630.87 426.81,576.04 444.98,557.86 444.98,535.89 444.98,450.01 461.77,433.22 v1(464,433.22)
RADIO_PA8: P201.8 U1.H13 | length 533
  Top Layer w4: v1(280,935.22) 283.76,938.98 v1@284.91,938.98 ; v1@284.91,937.71 286.17,938.98 U1.H13@318.9,938.98
  Bottom Layer w4: P201.8@265.55,490.16 273.17,497.78 269,501.95 269,550.85 273.17,555.02 273.17,800.71 273.17,820.79 243.89,850.08 243.89,921.74 254.37,932.22 277,932.22 v1(280,935.22)
RADIO_PA9: P201.10 U1.H12 | length 928.8
  Signal Layer 2 w4: v1@113.86,940.24 119.21,940.24 130.19,951.22 287.83,951.22 297.11,941.94 310.36,941.94 335.62,941.94 v2(338.58,938.98)
  Signal Layer 5 w4: v1(112.85,941.08) 112.85,938.44 160.56,890.74 160.56,832.46 136.07,807.97 136.07,567.67 182.69,521.04 201.65,521.04 269.85,452.84 286.21,452.84 v1(305.5,433.55)
  Bottom Layer w4: v1(305.5,433.55) 305.5,467.03 322.09,483.62 P201.10@315.55,490.16
RADIO_PB6: P201.12 U1.F12 | length 999.6
  Signal Layer 2 w4: v1(120.72,878.06) 121.15,877.63 132.1,877.63 153.98,855.75 239.85,855.75 262.48,833.12 280.84,833.12 286,838.28 286,843.85 295.37,853.22 300.94,853.22 323.94,876.22 323.94,882.95 338.58,897.6 v2(338.58,899.61)
  Signal Layer 5 w4: v1(120.72,878.06) 136.56,862.22 136.56,842.4 112.07,817.91 112.07,557.73 172.75,497.04 190.22,497.04 237.49,449.77 237.49,439.77 271.11,406.15 351.03,406.15 376.92,432.04 v1(382.86,432.04)
  Bottom Layer w4: P201.12@365.55,464.91 382.86,447.6 v1(382.86,432.04)
RADIO_PB7: P201.14 U1.E13 | length 496.1
  Top Layer w4: v1(296,882.22) 295.6,882.22 294.22,883.6 296.85,886.22 303.15,879.92 U1.E13@318.9,879.92
  Bottom Layer w4: v1(296,882.22) 296,884.22 311.51,868.71 311.51,856.48 325.07,842.92 325.07,776.66 313.46,765.05 313.46,710.28 314.29,709.45 402.81,620.93 402.81,523.94 415.55,511.2 P201.14@415.55,490.16 409,483.61 P201.14@409.62,482.99
RADIO_PB8: P201.17 U1.E12 | length 1135.8
  Signal Layer 2 w4: v1(120.56,852.83) 115.48,847.75 236.53,847.75 263.06,821.22 308.63,821.22 318.08,830.68 318.08,859.05 338.58,879.55 v2(338.58,879.92)
  Signal Layer 5 w4: v1(120.56,852.83) 120.56,837.72 104.07,821.22 104.07,554.41 169.44,489.04 186.9,489.04 229.49,446.46 229.49,436.46 268.12,397.83 485.37,397.83 506.83,419.3 v1(506.83,429.18)
  Bottom Layer w4: v1@506.13,427.92 506.13,402.72 515.55,393.29 P201.17@515.55,375.98
RADIO_PB9: P201.18 U1.D13 | length 725.1
  Top Layer w4: v1(269.1,849.12) 269.1,849.34 280,860.24 U1.D13@318.9,860.24
  GND Layer 3 w4: v1(269.1,849.12) 269.69,849.7 v1@269.69,850.39
  Signal Layer 5 w4: v1(286.8,541.2) 286.8,542.65 304.37,560.22 321.28,560.22 329.28,552.22 405.37,552.22 421.37,568.22 434.63,568.22 443.32,559.53 470.34,559.53 491.87,538 v1(511,538)
  Bottom Layer w4: v1(269.1,849.12) 269.1,836.18 281.17,824.11 281.17,562.23 286.8,556.61 v1(286.8,541.2) ; v1(511,538) 515.55,533.45 P201.18@515.55,491.09 ; v1@516.61,538 516.61,492.15 P201.18@515.55,491.09 ; P201.18@515.55,491.09 P201.18@515.55,490.16 515.08,490.63 P201.18@515.55,491.09
RADIO_PB10: P200.4 U1.D12 | length 943.7
  Top Layer w4: U1.D12@334.34,860.24 v2(338.58,860.24)
  Signal Layer 2 w4: v1(72.56,856.3) 84.44,856.3 103.91,836.83 133.19,836.83 136.1,839.75 233.22,839.75 259.75,813.22 311.94,813.22 326.08,827.36 326.08,847.74 v2(338.58,860.24)
  Bottom Layer w4: v1(72.56,856.3) 88.82,872.55 88.82,1026.38 63.56,1051.63 63.56,1207.48 136.12,1280.03 136.12,1383.37 165.55,1412.8 P200.4@165.55,1418.67
RADIO_PB11: P200.34 U1.D11 | length 1613
  Top Layer w4: U1.D11@358.27,860.24 360.24,862.2 359.51,862.94 v1(359.51,879.19)
  Signal Layer 2 w4: v1(359.51,879.19) 359.51,830.94 382.51,807.94 399.25,807.94 433,774.19 433,724.53 451.54,705.99 451.54,683.37 460.92,673.99 560,673.99 600.27,633.72 790.85,633.72 798.4,626.17 830.11,626.17 840.25,636.31 878.14,636.31 895.51,653.68 914.54,653.68 v1(917,651.22)
  Bottom Layer w4: P200.34@915.55,1435.04 915.55,1408.31 914.44,1408.31 894.12,1387.98 894.12,1264.15 840,1210.04 840,992.36 885,947.36 885,884.01 902.82,866.19 902.82,686.07 917,671.89 v1(917,651.22)
RADIO_PB12: P200.33 U1.C13 | length 1411.9
  Top Layer w4: v1(302,837.22) 305.33,840.55 U1.C13@318.9,840.55
  Signal Layer 5 w4: v1(302,837.22) 314.06,825.16 447.29,825.16 473.23,799.22 545.05,799.22 564.33,779.94 688.2,779.94 712.79,804.54 789.07,804.54 854.82,738.79 854.82,707.28 865.34,696.76 912.23,696.76 v1(921.51,706.03)
  Bottom Layer w4: P200.33@915.55,1320.87 915.55,1297.22 902.12,1283.79 902.12,1260.84 848,1206.72 848,995.67 893,950.67 893,887.32 910.82,869.5 910.82,716.72 v1(921.51,706.03)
